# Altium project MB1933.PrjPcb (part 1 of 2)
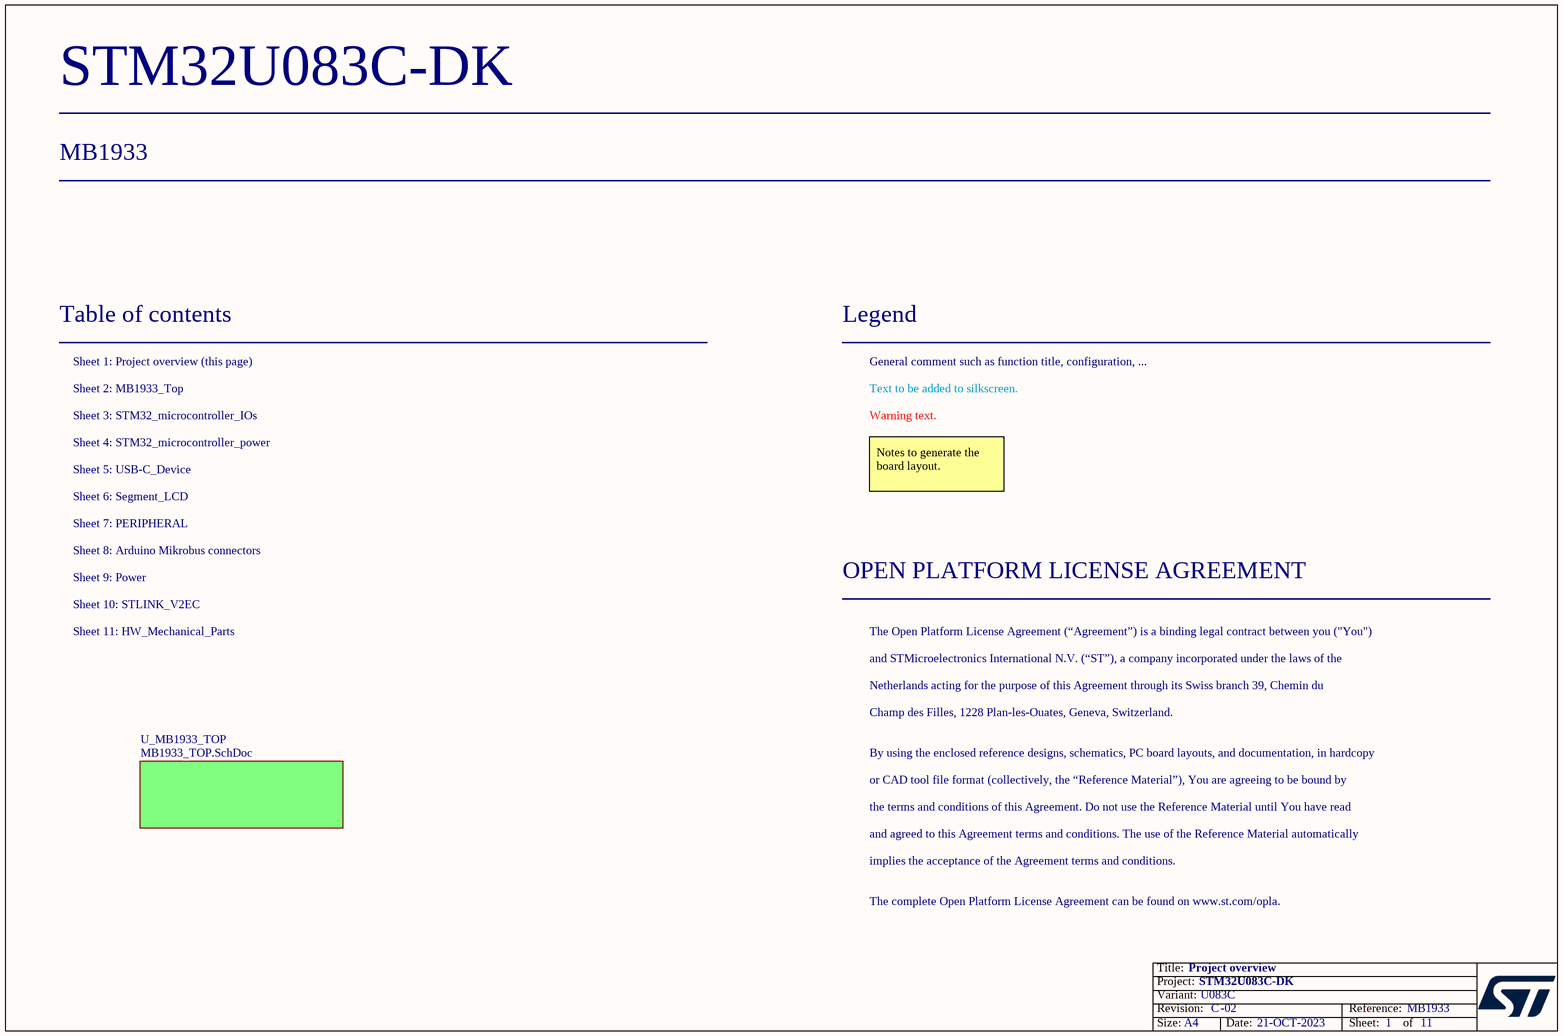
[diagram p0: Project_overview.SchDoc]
VariantName: U083C; Board_Reference: MB1933; Board_PCB_Revision: C; Board_Name: STM32U083C-DK; Board_Document_Date: 21-OCT-2023; Board_Assembly_Revision: 02
11 sheets, 236 parts. Net scope: flat (ports and power ports of the same name join across sheets).
Board file: MB1933.PcbDoc
Sheets:
  Project_overview.SchDoc
    U_MB1933_TOP = MB1933_TOP.SchDoc
      U_STM32_microcontroller_IOs = STM32_microcontroller_IOs.SchDoc
      U_HW_Mechanical_Parts = HW_Mechanical_Parts.SchDoc
      U_Power = Power.SchDoc
      U_Segment_LCD = Segment_LCD.SchDoc
      U_STLINK_V2EC = STLINK_V2EC.SchDoc
      U_USB-C_Device = USB-C_Device.SchDoc
      U_PERIPHERAL = PERIPHERAL.SchDoc
      U_STM32_microcontroller_power = STM32_microcontroller_power.SchDoc
      U_Arduino_Mikrobus_connectors = Arduino_Mikrobus_connectors.SchDoc

## Sheet Project_overview.SchDoc: Project overview
size A4; Date: Not used; ApprovedBy: Not used; CheckedBy: Not used; Author: Not used; CompanyName: STMicroelectronics; DrawnBy: Not used; Engineer: Not used; Organization: Not used; Address1: Not used; Address2: Not used; Address3: Not used; Address4: Not used; DocumentNumber: 1; Revision: Not used; SheetNumber: 1; SheetTotal: 11

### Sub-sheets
U_MB1933_TOP = MB1933_TOP.SchDoc: no entries

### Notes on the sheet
- Table of contents
- Sheet 1: Project overview (this page)
- Legend
- General comment such as function title, configuration, ...
- Sheet 2: MB1933_Top
- Sheet 3: STM32_microcontroller_IOs
- Sheet 4: STM32_microcontroller_power
- Text to be added to silkscreen.
- Warning text.
- Sheet 6: Segment_LCD
- Sheet 5: USB-C_Device
- Notes to generate the board layout.
- Sheet 9: Power
- Sheet 8: Arduino Mikrobus connectors
- Sheet 7: PERIPHERAL
- OPEN PLATFORM LICENSE AGREEMENT
- Sheet 10: STLINK_V2EC
- Sheet 11: HW_Mechanical_Parts
- The Open Platform License Agreement (“Agreement”) is a binding legal contract between you ("You")
- and STMicroelectronics International N.V. (“ST”), a company incorporated under the laws of the
- Netherlands acting for the purpose of this Agreement through its Swiss branch 39, Chemin du
- Champ des Filles, 1228 Plan-les-Ouates, Geneva, Switzerland.
- By using the enclosed reference designs, schematics, PC board layouts, and documentation, in hardcopy
- or CAD tool file format (collectively, the “Reference Material”), You are agreeing to be bound by
- the terms and conditions of this Agreement. Do not use the Reference Material until You have read
- and agreed to this Agreement terms and conditions. The use of the Reference Material automatically
- implies the acceptance of the Agreement terms and conditions.
- The complete Open Platform License Agreement can be found on www.st.com/opla.

## Sheet MB1933_TOP.SchDoc: TOP
size A4; CompanyName: STMicroelectronics; Organization: Microcontrollers Division; SheetNumber: 2; SheetTotal: 11
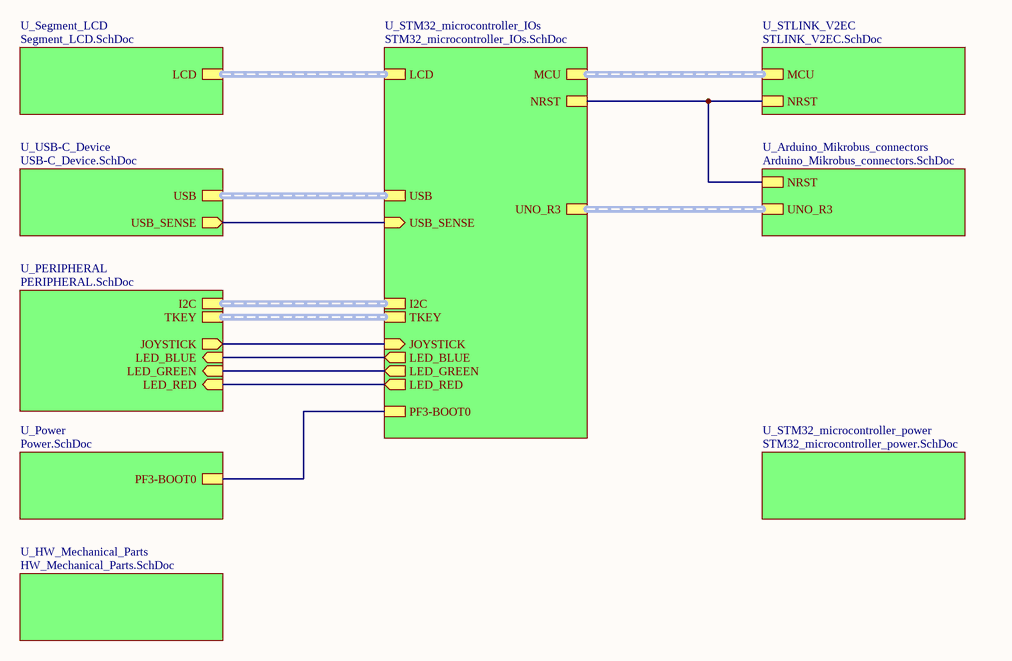
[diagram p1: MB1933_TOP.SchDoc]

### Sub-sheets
U_Arduino_Mikrobus_connectors = Arduino_Mikrobus_connectors.SchDoc: NRST, UNO_R3 (harness UNO_R3)
U_HW_Mechanical_Parts = HW_Mechanical_Parts.SchDoc: no entries
U_PERIPHERAL = PERIPHERAL.SchDoc: LED_BLUE (in), LED_GREEN (in), LED_RED (in), JOYSTICK (out), I2C (harness I2C), TKEY (harness TKEY)
U_Power = Power.SchDoc: PF3-BOOT0
U_Segment_LCD = Segment_LCD.SchDoc: LCD (harness LCD)
U_STLINK_V2EC = STLINK_V2EC.SchDoc: MCU (harness MCU), NRST
U_STM32_microcontroller_IOs = STM32_microcontroller_IOs.SchDoc: NRST, UNO_R3 (harness UNO_R3), JOYSTICK (in), LCD (harness LCD), I2C (harness I2C), TKEY (harness TKEY), LED_GREEN (out), LED_RED (out), LED_BLUE (out), USB (harness USB), PF3-BOOT0, MCU (harness MCU), USB_SENSE (in)
U_STM32_microcontroller_power = STM32_microcontroller_power.SchDoc: no entries
U_USB-C_Device = USB-C_Device.SchDoc: USB (harness USB), USB_SENSE (out)

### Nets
(unnamed): sheet U_STM32_microcontroller_IOs/NRST, sheet U_STLINK_V2EC/NRST, sheet U_Arduino_Mikrobus_connectors/NRST
(unnamed): sheet U_STM32_microcontroller_IOs/JOYSTICK, sheet U_PERIPHERAL/JOYSTICK  [a separate net that carries the same name]
(unnamed): sheet U_STM32_microcontroller_IOs/LED_GREEN, sheet U_PERIPHERAL/LED_GREEN  [a separate net that carries the same name]
(unnamed): sheet U_STM32_microcontroller_IOs/LED_RED, sheet U_PERIPHERAL/LED_RED  [a separate net that carries the same name]
(unnamed): sheet U_STM32_microcontroller_IOs/LED_BLUE, sheet U_PERIPHERAL/LED_BLUE  [a separate net that carries the same name]
(unnamed): sheet U_STM32_microcontroller_IOs/PF3-BOOT0, sheet U_Power/PF3-BOOT0  [a separate net that carries the same name]
(unnamed): sheet U_STM32_microcontroller_IOs/USB_SENSE, sheet U_USB-C_Device/USB_SENSE  [a separate net that carries the same name]

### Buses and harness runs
harness sheet U_Arduino_Mikrobus_connectors/UNO_R3 = sheet U_STM32_microcontroller_IOs/UNO_R3
harness sheet U_PERIPHERAL/I2C = sheet U_STM32_microcontroller_IOs/I2C
harness sheet U_PERIPHERAL/TKEY = sheet U_STM32_microcontroller_IOs/TKEY
harness sheet U_Segment_LCD/LCD = sheet U_STM32_microcontroller_IOs/LCD
harness sheet U_STLINK_V2EC/MCU = sheet U_STM32_microcontroller_IOs/MCU
harness sheet U_STM32_microcontroller_IOs/USB = sheet U_USB-C_Device/USB

## Sheet STM32_microcontroller_IOs.SchDoc: STM32_microcontroller_IOs
size A4; CompanyName: STMicroelectronics; Organization: Microcontrollers Division; SheetNumber: 3; SheetTotal: 11
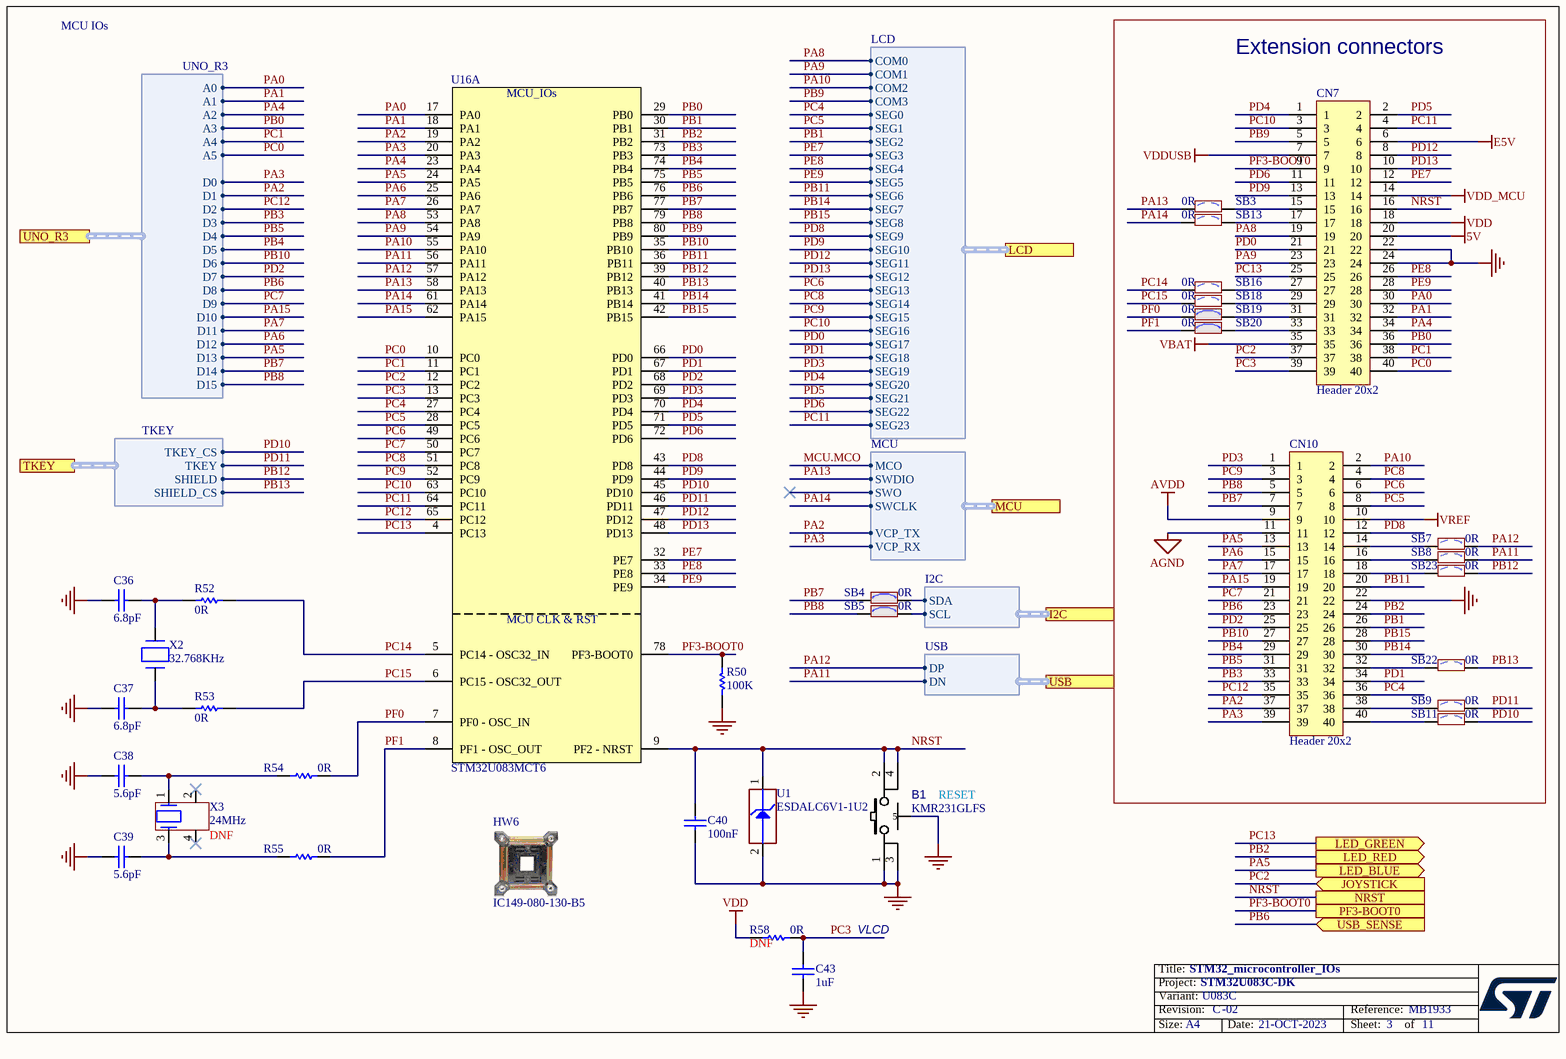
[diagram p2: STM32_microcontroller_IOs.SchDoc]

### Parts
B1  value KMR231GLFS  [SWI_C&K_Y78B23110FP__ITT_KMR231GLFS]  (hidden comment: SW-PUSH-CMS_KMR2_BLACK)
C36  value 6.8pF  [C0402]  (hidden comment: Capacitor)
C37  value 6.8pF  [C0402]  (hidden comment: Capacitor)
C38  value 5.6pF  [C0402]  (hidden comment: Capacitor)
C39  value 5.6pF  [C0402]  (hidden comment: Capacitor)
C40  value 100nF  [C0402]  (hidden comment: Capacitor)
C43  value 1uF  [C0603]  (hidden comment: Capacitor)
CN7  Header 20x2  [CON_SAMTEC_TSW-120-09-G-D]
CN10  Header 20x2  [CON_SAMTEC_TSW-120-09-G-D]
HW6  value IC149-080-130-B5  (hidden comment: SOCKET_LQFP)  (mechanical)
R50  value 100K  [R0402]  (hidden comment: Resistor)
R52  value 0R  [R0402]  (hidden comment: Resistor)
R53  value 0R  [R0402]  (hidden comment: Resistor)
R54  value 0R  [R0402]  (hidden comment: Resistor)
R55  value 0R  [R0402]  (hidden comment: Resistor)
R58  value 0R  [R0402]  (hidden comment: Resistor)
SB3  value 0R  [SOLDER-BRIDGE_R0603-0R]  (hidden comment: SB_OFF)
SB4  value 0R  [SOLDER-BRIDGE_R0603-0R]  (hidden comment: SB_ON)
SB5  value 0R  [SOLDER-BRIDGE_R0603-0R]  (hidden comment: SB_ON)
SB7  value 0R  [SOLDER-BRIDGE_R0603-0R]  (hidden comment: SB_OFF)
SB8  value 0R  [SOLDER-BRIDGE_R0603-0R]  (hidden comment: SB_OFF)
SB9  value 0R  [SOLDER-BRIDGE_R0603-0R]  (hidden comment: SB_OFF)
SB11  value 0R  [SOLDER-BRIDGE_R0603-0R]  (hidden comment: SB_OFF)
SB13  value 0R  [SOLDER-BRIDGE_R0603-0R]  (hidden comment: SB_OFF)
SB16  value 0R  [SOLDER-BRIDGE_R0603-0R]  (hidden comment: SB_OFF)
SB18  value 0R  [SOLDER-BRIDGE_R0603-0R]  (hidden comment: SB_OFF)
SB19  value 0R  [SOLDER-BRIDGE_R0603-0R]  (hidden comment: SB_ON)
SB20  value 0R  [SOLDER-BRIDGE_R0603-0R]  (hidden comment: SB_ON)
SB22  value 0R  [SOLDER-BRIDGE_R0603-0R]  (hidden comment: SB_OFF)
SB23  value 0R  [SOLDER-BRIDGE_R0603-0R]  (hidden comment: SB_OFF)
U1  value ESDALC6V1-1U2  [ESD_ST0201]  (hidden comment: ESD-TRANSIL)
U16  STM32U083MCT6  [ICC_LQFP80_12X12_P050_SOCKET_YAMAICHI_IC149-080-130-B5]  (part A of 2)
X2  value 32.768KHz  [CRY_NX2012SA_2P]  (hidden comment: XTAL_2_PINS)
X3  value 24MHz  [CRY_NX2016SA_4P]  (hidden comment: XTAL_4_PINS)

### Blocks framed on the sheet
Extension connectors: CN7 CN10 SB3 SB7-SB9 SB11 SB13 SB16 SB18-SB20 SB22 SB23

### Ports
I2C (harness I2C), JOYSTICK (in), LCD (harness LCD), LED_BLUE (out), LED_GREEN (out), LED_RED (out), MCU (harness MCU), NRST, PF3-BOOT0, TKEY (harness TKEY), UNO_R3 (harness UNO_R3), USB (harness USB), USB_SENSE (in)

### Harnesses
TKEY: TKEY_CS, TKEY, SHIELD, SHIELD_CS
LCD: COM0, COM1, COM2, COM3, SEG0, SEG1, SEG2, SEG3, SEG4, SEG5, SEG6, SEG7, SEG8, SEG9, SEG10, SEG11, SEG12, SEG13, SEG14, SEG15, SEG16, SEG17, SEG18, SEG19, SEG20, SEG21, SEG22, SEG23
I2C: SDA, SCL
USB: DP, DN
UNO_R3: A0, A1, A2, A3, A4, A5, D0, D1, D2, D3, D4, D5, D6, D7, D8, D9, D10, D11, D12, D13, D14, D15
MCU: MCO, SWDIO, SWO, VCP_TX, SWCLK, VCP_RX

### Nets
5V: CN7.20
AGND: CN10.11
AVDD: CN10.9
E5V: CN7.6
GND: B1.1 B1.3 B1.5 C36.1 C37.1 C38.1 C39.1 C40.1 C43.1 CN7.22 CN7.24 CN10.22 R50.2 U1.2(GND)
VBAT: CN7.35
VDD: CN7.18 R58.1
VDD_MCU: CN7.14
VDDUSB: CN7.7
VREF: CN10.10
I2C_SCL: SB5.2 ; port I2C.SCL
I2C_SDA: SB4.2 ; port I2C.SDA
NRST: B1.2 B1.4 C40.2 CN7.16 U1.1(IO1) U16.9(PF2_-_NRST) ; port NRST
PA0: CN7.30 U16.17(PA0) ; port UNO_R3.A0  [project net ARD_A0]
PA1: CN7.32 U16.18(PA1) ; port UNO_R3.A1  [project net ARD_A1]
PA2: CN10.37 U16.19(PA2) ; port UNO_R3.D1, port MCU.VCP_TX  [project net ARD_D1]
PA3: CN10.39 U16.20(PA3) ; port UNO_R3.D0, port MCU.VCP_RX  [project net ARD_D0]
PA4: CN7.34 U16.23(PA4) ; port UNO_R3.A2  [project net ARD_A2]
PA5: CN10.13 U16.24(PA5) ; port LED_BLUE, port UNO_R3.D13  [project net ARD_D13]
PA6: CN10.15 U16.25(PA6) ; port UNO_R3.D12  [project net ARD_D12]
PA7: CN10.17 U16.26(PA7) ; port UNO_R3.D11  [project net ARD_D11]
PA8: CN7.19 U16.53(PA8) ; port LCD.COM0  [project net COM0]
PA9: CN7.23 U16.54(PA9) ; port LCD.COM1  [project net COM1]
PA10: CN10.2 U16.55(PA10) ; port LCD.COM2  [project net COM2]
PA11: SB8.2 U16.56(PA11) ; port USB.DN
PA12: SB7.2 U16.57(PA12) ; port USB.DP
PA13: SB3.1 U16.58(PA13) ; port MCU.SWDIO  [project net MCU.SWDIO]
PA14: SB13.1 U16.61(PA14) ; port MCU.SWCLK  [project net MCU.SWCLK]
PA15: CN10.19 U16.62(PA15) ; port UNO_R3.D10  [project net ARD_D10]
PB0: CN7.36 U16.29(PB0) ; port UNO_R3.A3  [project net ARD_A3]
PB1: CN10.26 U16.30(PB1) ; port LCD.SEG2
PB2: CN10.24 U16.31(PB2) ; port LED_RED
PB3: CN10.33 U16.73(PB3) ; port UNO_R3.D3  [project net ARD_D3]
PB4: CN10.29 U16.74(PB4) ; port UNO_R3.D5  [project net ARD_D5]
PB5: CN10.31 U16.75(PB5) ; port UNO_R3.D4  [project net ARD_D4]
PB6: CN10.23 U16.76(PB6) ; port USB_SENSE, port UNO_R3.D8  [project net ARD_D8]
PB7: CN10.7 SB4.1 U16.77(PB7) ; port UNO_R3.D14  [project net ARD_D14]
PB8: CN10.5 SB5.1 U16.79(PB8) ; port UNO_R3.D15  [project net ARD_D15]
PB9: CN7.5 U16.80(PB9) ; port LCD.COM3  [project net COM3]
PB10: CN10.27 U16.35(PB10) ; port UNO_R3.D6  [project net ARD_D6]
PB11: CN10.20 U16.36(PB11) ; port LCD.SEG6
PB12: SB23.2 U16.39(PB12) ; port TKEY.SHIELD
PB13: SB22.2 U16.40(PB13) ; port TKEY.SHIELD_CS
PB14: CN10.30 U16.41(PB14) ; port LCD.SEG7
PB15: CN10.28 U16.42(PB15) ; port LCD.SEG8
PC0: CN7.40 U16.10(PC0) ; port UNO_R3.A5  [project net ARD_A5]
PC1: CN7.38 U16.11(PC1) ; port UNO_R3.A4  [project net ARD_A4]
PC2: CN7.37 U16.12(PC2) ; port JOYSTICK
PC3: C43.2 CN7.39 R58.2 U16.13(PC3)
PC4: CN10.36 U16.27(PC4) ; port LCD.SEG0
PC5: CN10.8 U16.28(PC5) ; port LCD.SEG1
PC6: CN10.6 U16.49(PC6) ; port LCD.SEG13
PC7: CN10.21 U16.50(PC7) ; port UNO_R3.D9  [project net ARD_D9]
PC8: CN10.4 U16.51(PC8) ; port LCD.SEG14
PC9: CN10.3 U16.52(PC9) ; port LCD.SEG15
PC10: CN7.3 U16.63(PC10) ; port LCD.SEG16
PC11: CN7.4 U16.64(PC11) ; port LCD.SEG23
PC12: CN10.35 U16.65(PC12) ; port UNO_R3.D2  [project net ARD_D2]
PC13: CN7.25 U16.4(PC13) ; port LED_GREEN
PC14: R52.2 SB16.1 U16.5(PC14_-_OSC32_IN)
PC15: R53.2 SB18.1 U16.6(PC15_-_OSC32_OUT)
PD0: CN7.21 U16.66(PD0) ; port LCD.SEG17
PD1: CN10.34 U16.67(PD1) ; port LCD.SEG18
PD2: CN10.25 U16.68(PD2) ; port UNO_R3.D7  [project net ARD_D7]
PD3: CN10.1 U16.69(PD3) ; port LCD.SEG19
PD4: CN7.1 U16.70(PD4) ; port LCD.SEG20
PD5: CN7.2 U16.71(PD5) ; port LCD.SEG21
PD6: CN7.11 U16.72(PD6) ; port LCD.SEG22
PD8: CN10.12 U16.43(PD8) ; port LCD.SEG9
PD9: CN7.13 U16.44(PD9) ; port LCD.SEG10
PD10: SB11.2 U16.45(PD10) ; port TKEY.TKEY_CS
PD11: SB9.2 U16.46(PD11) ; port TKEY.TKEY
PD12: CN7.8 U16.47(PD12) ; port LCD.SEG11
PD13: CN7.10 U16.48(PD13) ; port LCD.SEG12
PE7: CN7.12 U16.32(PE7) ; port LCD.SEG3
PE8: CN7.26 U16.33(PE8) ; port LCD.SEG4
PE9: CN7.28 U16.34(PE9) ; port LCD.SEG5
PF0: R54.2 SB19.1 U16.7(PF0_-_OSC_IN)
PF1: R55.2 SB20.1 U16.8(PF1_-_OSC_OUT)
PF3-BOOT0: CN7.9 R50.1 U16.78(PF3-BOOT0) ; port PF3-BOOT0
NetC36_2: C36.2 R52.1 X2.2(X2)
NetC37_2: C37.2 R53.1 X2.1(X1)
NetC38_2: C38.2 R54.1 X3.1
NetC39_2: C39.2 R55.1 X3.3
NetCN7_15: CN7.15 SB3.2
NetCN7_17: CN7.17 SB13.2
NetCN7_27: CN7.27 SB16.2
NetCN7_29: CN7.29 SB18.2
NetCN7_31: CN7.31 SB19.2
NetCN7_33: CN7.33 SB20.2
NetCN10_14: CN10.14 SB7.1
NetCN10_16: CN10.16 SB8.1
NetCN10_18: CN10.18 SB23.1
NetCN10_32: CN10.32 SB22.1
NetCN10_38: CN10.38 SB9.1
NetCN10_40: CN10.40 SB11.1

Not connected (* = marked no-connect by the designer): X3 2* 4*

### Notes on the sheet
- MCU IOs
- (near X3) DNF
- (near B1) RESET
- (near R58) DNF
- VLCD

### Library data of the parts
B1 = MCD-01485: Switch tactile, SPST-NO, 32V, 50mA, 2.8x4.6mm; Part_Type: Misc; Part_Preference: Recommended; Manufacturer: C&K; Component_Country_Of_Origin: France; ShowFields: YES; ID: 3585; Order_Code_RS: 505-9192
C36 C37 = MCD-00674: Capacitor, MLCC, 6.8pF, 50V, NPO, +/-0.25pF, 0402, T=0.5mm; Manufacturer_Part_Number: CC0402CRNPO9BN6R8; Manufacturer: YAGEO; Part_Preference: Recommended; Component_Country_Of_Origin: China; ShowFields: YES; ID: 3068
C38 C39 = MCD-01374: Capacitor, MLCC, 5.6pF, 50V, NPO, +/-0.1pF, 0402, T=0.5mm; Manufacturer_Part_Number: CC0402BRNPO9BN5R6; Manufacturer: YAGEO; Part_Preference: Recommended; Component_Country_Of_Origin: China; ShowFields: YES; ID: 3474
C40 = MCD-00006: Capacitor, MLCC, 100nF, 16V, X7R, +/-10%, 0402, T=0.5mm; Part_Preference: Recommended; Manufacturer: YAGEO; Manufacturer_Part_Number: CC0402KRX7R7BB104; Partial_Alternate_Internal_Part_Number: MCD-03299; Order_Code_RS: 9402047; Component_Country_Of_Origin: China; ShowFields: YES; ID: 2474
C43 = MCD-00010: Capacitor, MLCC, 1uF, 16V, X5R, +/-10%, 0603, T=0.8mm; Manufacturer_Part_Number: CC0603KRX5R7BB105; Manufacturer: YAGEO; Part_Preference: Recommended; Order_Code_RS: 2370680; Component_Country_Of_Origin: China; ShowFields: YES; ID: 2470
CN7 CN10 = MCD-03295: Header, 20x2, 2.54mm, VR, TH, T=5.84mm/10.16mm; Part_Type: Connector; Part_Preference: Recommended; Manufacturer: SAMTEC; Manufacturer_Part_Number: TSW-120-09-G-D; ShowFields: YES; ID: 5411; Component_Country_Of_Origin: USA°
HW6 = MCD-03172: Socket_IC, LQFP80, IC149 series, pitch 0.5mm, T=11mm; Part_Preference: Recommended; Manufacturer: YAMAICHI; ShowFields: YES; ID: 5288
R50 = MCD-00059: Resistor, 100K, 0402, +/-1%, 1/16W; Manufacturer_Part_Number: RC0402FR-07100KL; Manufacturer: YAGEO; Part_Preference: Recommended; Partial_Alternate_Internal_Part_Number: MCD-03301; Order_Code_RS: 2421891; Component_Country_Of_Origin: China; ShowFields: YES; ID: 2533
R52-R55 R58 = MCD-00052: Resistor, 0R, 0402, +/-5%, 1/16W; Manufacturer_Part_Number: RC0402JR-070RL; Manufacturer: YAGEO; Part_Preference: Recommended; Order_Code_RS: 9232516RL; Component_Country_Of_Origin: China; ShowFields: YES; ID: 2540
SB3 SB9 SB11 SB13 SB16 SB18 SB22 SB23 = MCD-00072: Resistor, 0R, SB0603, 5%, 0.1W; Manufacturer_Part_Number: RC0603JR-070RL; Manufacturer: YAGEO; Part_Preference: Recommended; Manufacturer_HQ_COO: Unknown; Component_Country_Of_Origin: China; ShowFields: YES; ID: 2520; Order_Code_RS: 199-5647
SB4 SB5 SB19 SB20 = MCD-00071: Resistor, 0R, SB0603, 5%, 0.1W; Manufacturer_Part_Number: RC0603JR-070RL; Manufacturer: YAGEO; Part_Preference: Recommended; Manufacturer_HQ_COO: Unknown; ShowFields: YES; ID: 2521; Order_Code_RS: 199-5647; Component_Country_Of_Origin: China
SB7 SB8 = MCD-00072: Resistor, 0R, SB0603, 5%, 0.1W; Manufacturer_Part_Number: RC0603JR-070RL; Manufacturer: YAGEO; Part_Preference: Recommended; Manufacturer_HQ_COO: Unknown; ShowFields: YES; ID: 2520; Component_Country_Of_Origin: China; Order_Code_RS: 199-5647
U1 = MCD-00170: Diode, ESD TVS, 3V, 100nA, 8V, ST0201; Manufacturer: STMICROELECTRONICS; BMS_Part_Number: 9151132; Part_Preference: Recommended; Manufacturer_HQ_COO: EU; Component_Country_Of_Origin: China; ShowFields: YES; ID: 2696; Order_Code_RS: 795-8404
U16 = MCD-03131: Arm® Cortex®-M0+ 32-bit MCU,  256K Flash memory, with LQFP80 socket footprint (IC149-080-130-B5); Part_Type: IC; Part_Preference: Recommended; Manufacturer: STMICROELECTRONICS; Component_Country_Of_Origin: Unknown; ShowFields: YES; ID: 5247
X2 = MCD-01479: Crystal, 32.768kHz, 6pF, +/-20ppm, 80K, 2.05x1.2mm; Part_Type: Crystal_Osc; Manufacturer_Part_Number: NX2012SA-32.768KHZ-EXS00A-MU00527; Manufacturer: NDK; BMS_Part_Number: 9157049; Part_Preference: Recommended; Component_Country_Of_Origin: Unknown; ShowFields: YES; ID: 3579
X3 = MCD-01036: Crystal, 24MHz, 6pF, +/-20ppm, 80R, 2x1.6mm; Part_Type: Crystal_Osc; Manufacturer_Part_Number: NX2016SA-24MHZ-EXS00A-CS10820; Manufacturer: NDK; BMS_Part_Number: 9157045; Part_Preference: Recommended; Component_Country_Of_Origin: Unknown; ShowFields: YES; ID: 2989

## Sheet HW_Mechanical_Parts.SchDoc: HW Mechanical parts
size A4; SheetNumber: 11; SheetTotal: 11
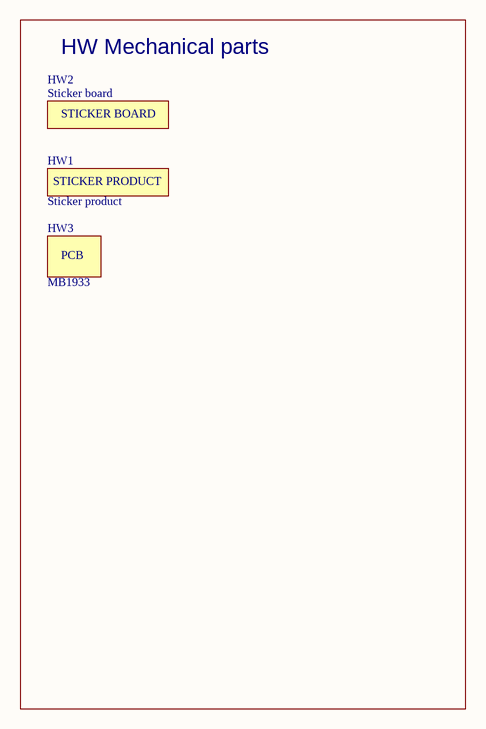
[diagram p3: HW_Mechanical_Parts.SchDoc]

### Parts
HW1  value Sticker product  [STICKER_PRODUCT_25X9]  (hidden comment: STICKER_PRODUCT)  (no BOM)
HW2  value Sticker board  [STICKER_BOARD_25X9]  (hidden comment: STICKER_BOARD)  (no BOM)
HW3  value MB1933  (hidden comment: PCB)  (no BOM)

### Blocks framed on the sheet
HW Mechanical parts: HW1-HW3

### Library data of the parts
HW1 = MCD-00547: Sticker product 25x9 mm; Part_Type: Misc; Part_Preference: Recommended; ShowFields: YES; ID: 3197
HW2 = MCD-00235: Sticker Board 25x9 mm; Part_Type: Misc; Part_Preference: Recommended; ShowFields: YES; ID: 2632
HW3 = MCD-03168: MB1933 PCB; Part_Preference: Recommended; ShowFields: YES; ID: 5284

## Sheet Power.SchDoc: Power
size A4; CompanyName: STMicroelectronics; Organization: Microcontrollers Division; SheetNumber: 9; SheetTotal: 11
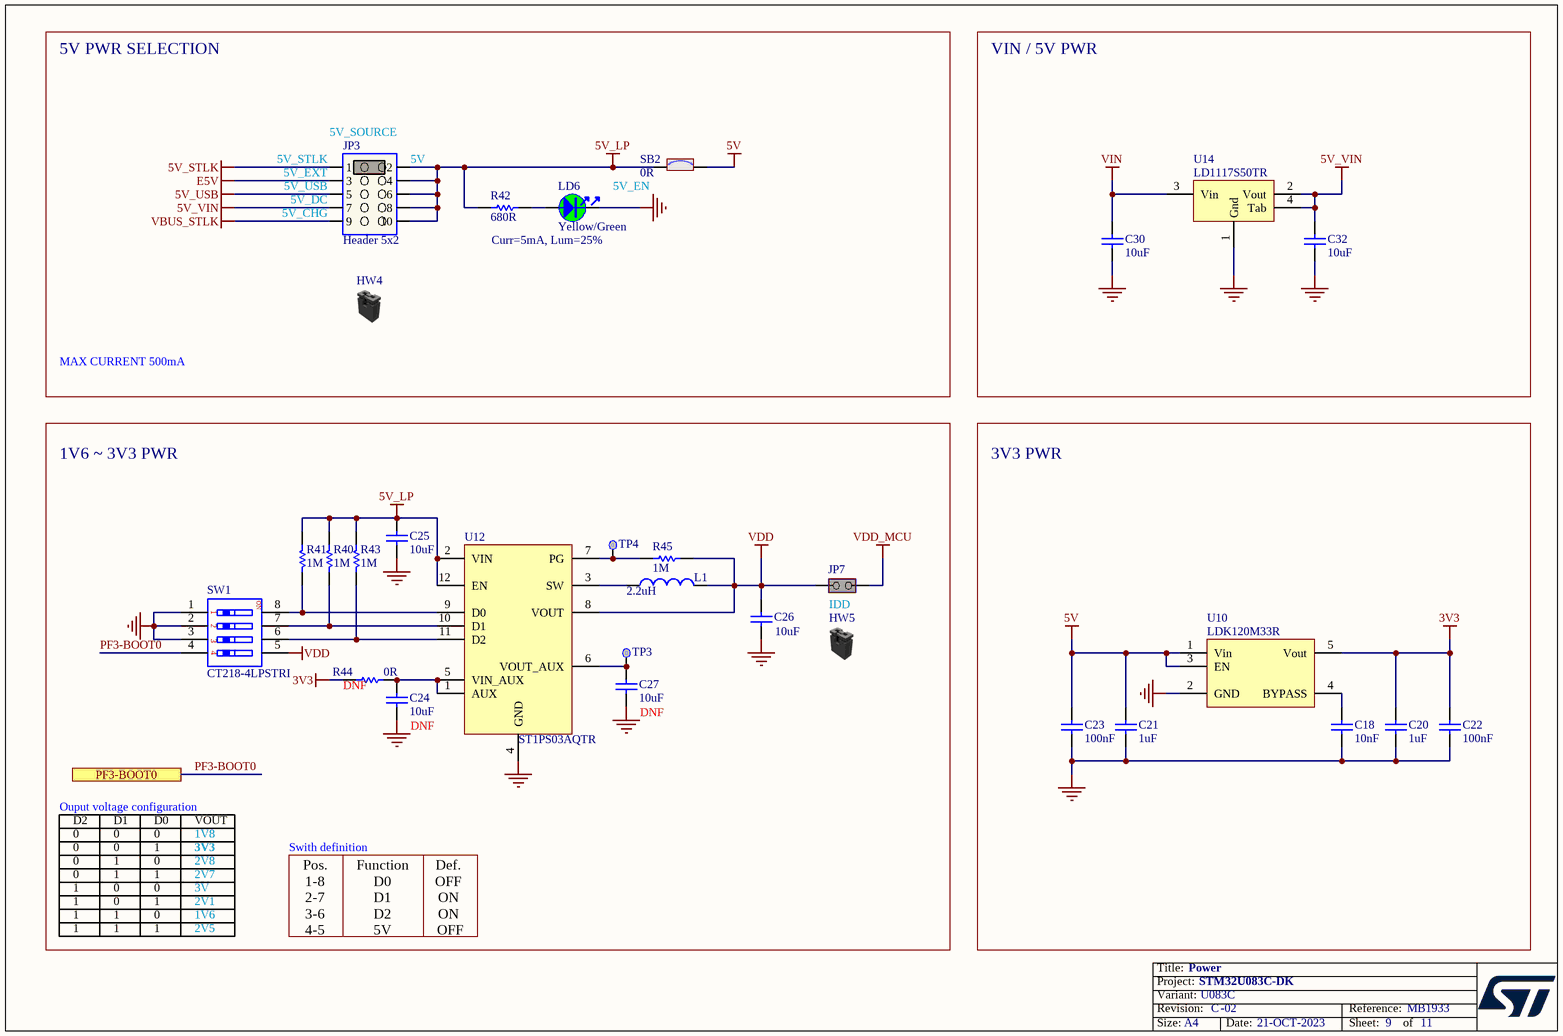
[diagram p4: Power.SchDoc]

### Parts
C18  value 10nF  [C0402]  (hidden comment: Capacitor)
C20  value 1uF  [C0603]  (hidden comment: Capacitor)
C21  value 1uF  [C0603]  (hidden comment: Capacitor)
C22  value 100nF  [C0402]  (hidden comment: Capacitor)
C23  value 100nF  [C0402]  (hidden comment: Capacitor)
C24  value 10uF  [C0603]  (hidden comment: Capacitor)
C25  value 10uF  [C0603]  (hidden comment: Capacitor)
C26  value 10uF  [C0603]  (hidden comment: Capacitor)
C27  value 10uF  [C0603]  (hidden comment: Capacitor)
C30  value 10uF  [C0805]  (hidden comment: Capacitor)
C32  value 10uF  [C0805]  (hidden comment: Capacitor)
HW4  Shunt Black 2.54mm  (value not drawn)  (mechanical)
HW5  Shunt Black 2.54mm  (value not drawn)  (mechanical)
JP3  value Header 5x2  [CON_SAMTEC_TSW-105-07-X-D]  (hidden comment: Jumper_Header 5x2 Fitted 1-2)
JP7  Jumper_Header 2x1 Fitted  [CON_SAMTEC_TSW-102-07-G-S]  (value not drawn)
L1  value 2.2uH  [IND_TDK_VLS252010HBX-1]  (hidden comment: Inductor)
LD6  value Yellow/Green  [LED_0402_EVERLIGHT_16-213SYGC/S530-E3-TR8 _YELLOW-GREEN_1A2K_H0P45]  (hidden comment: LED_green)
R40  value 1M  [R0402]  (hidden comment: Resistor)
R41  value 1M  [R0402]  (hidden comment: Resistor)
R42  value 680R  [R0402]  (hidden comment: Resistor)
R43  value 1M  [R0402]  (hidden comment: Resistor)
R44  value 0R  [R0402]  (hidden comment: Resistor)
R45  value 1M  [R0402]  (hidden comment: Resistor)
SB2  value 0R  [SOLDER-BRIDGE_R0603-0R]  (hidden comment: SB_ON)
SW1  value CT218-4LPSTRI  [SWI_CTS_CTS218-4LP]  (hidden comment: SWITCH_4WAY)
TP3  Test Point  [TP_SMD_1MM]  (value not drawn)  (no BOM)
TP4  Test Point  [TP_SMD_1MM]  (value not drawn)  (no BOM)
U10  LDK120M33R  [REG_SOT23-5L]
U12  value ST1PS03AQTR  [ICC_TQFN12_2X1P7_P040]  (hidden comment: ST1PS03)
U14  LD1117S50TR  [REG_SOT223-TAB]

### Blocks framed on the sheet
5V PWR SELECTION: HW4 JP3 LD6 R42 SB2
VIN / 5V PWR: C30 C32 U14
1V6 ~ 3V3 PWR: C24-C27 HW5 JP7 L1 R40 R41 R43-R45 SW1 TP3 TP4 U12
3V3 PWR: C18 C20-C23 U10

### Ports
PF3-BOOT0

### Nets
3V3: C20.2 C22.2 R44.1 U10.5(Vout)
5V: C21.2 C23.2 SB2.2 U10.1(Vin) U10.3(EN)
5V_LP: C25.2 JP3.2 JP3.4 JP3.6 JP3.8 JP3.10 R40.1 R41.1 R42.1 R43.1 SB2.1 U12.2(VIN) U12.12(EN)
5V_STLK: JP3.1
5V_USB: JP3.5
5V_VIN: C32.2 JP3.7 U14.2(Vout) U14.4(Tab)
E5V: JP3.3
GND: C18.1 C20.1 C21.1 C22.1 C23.1 C24.1 C25.1 C26.1 C27.1 C30.1 C32.1 LD6.2 SW1.1 SW1.2 SW1.3 U10.2(GND) U12.4(GND) U14.1(Gnd)
VBUS_STLK: JP3.9
VDD: C26.2 JP7.2(NO) L1.2 R45.1 SW1.5 U12.8(VOUT)
VDD_MCU: JP7.1(COMMON)
VIN: C30.2 U14.3(Vin)
PF3-BOOT0: SW1.4 ; port PF3-BOOT0
NetC18_2: C18.2 U10.4(BYPASS)
NetC24_2: C24.2 R44.2 U12.1(AUX) U12.5(VIN_AUX)
NetC27_2: C27.2 TP3.1 U12.6(VOUT_AUX)
NetL1_1: L1.1 U12.3(SW)
NetLD6_1: LD6.1 R42.2
NetR40_2: R40.2 SW1.7 U12.10(D1)
NetR41_2: R41.2 SW1.8 U12.9(D0)
NetR43_2: R43.2 SW1.6 U12.11(D2)
NetR45_2: R45.2 TP4.1 U12.7(PG)

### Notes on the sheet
- (near JP3) 5V_STLK
- (near JP3) 5V_EXT
- (near JP3) 5V_SOURCE
- (near JP3) 5V
- (near JP3) 5V_USB
- (near JP3) 5V_CHG
- (near JP3) 5V_DC
- Curr=5mA, Lum=25%
- 5V_EN
- MAX CURRENT 500mA
- IDD
- (near R44) DNF
- (near C27) DNF
- (near C24) DNF
- Ouput voltage configuration
- D2
- 0
- D1
- D0
- 1
- VOUT
- 1V8
- 3V3
- Swith definition
- 2V8
- 2V7
- 3V
- 2V1
- 1V6
- 2V5
- Pos.
  1-8
  2-7
  3-6
  4-5
- Function
  D0
  D1
  D2
  5V
- Def.
  OFF
  ON
  ON
  OFF

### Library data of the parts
C18 = MCD-02198: Capacitor, MLCC, 10nF, 50V, X7R, +/-10%, 0402, T=0.5mm; Manufacturer_Part_Number: CC0402KRX7R9BB103; Manufacturer: YAGEO; Part_Preference: Recommended; Order_Code_RS: 6169644; Component_Country_Of_Origin: China; ShowFields: YES; ID: 4298
C20 C21 = MCD-00010: as C43 on sheet STM32_microcontroller_IOs
C22 C23 = MCD-00006: Capacitor, MLCC, 100nF, 16V, X7R, +/-10%, 0402, T=0.5mm; Manufacturer_Part_Number: CC0402KRX7R7BB104; Manufacturer: YAGEO; Part_Preference: Recommended; Partial_Alternate_Internal_Part_Number: MCD-03299; Order_Code_RS: 9402047; Component_Country_Of_Origin: China; ShowFields: YES; ID: 2474
C24-C27 = MCD-00099: Capacitor, MLCC, 10uF, 10V, X5R, +/-10%, 0603, T=0.8mm; Manufacturer_Part_Number: GRM188R61A106KE69D; Manufacturer: MURATA; Part_Preference: Recommended; Partial_Alternate_Internal_Part_Number: MCD-03152; Order_Code_RS: 2494233; Component_Country_Of_Origin: Japan°°; ShowFields: YES; ID: 2770
C30 C32 = MCD-00014: Capacitor, MLCC, 10uF, 25V, X5R, +/-10%, 0805, T=0.85mm; Manufacturer_Part_Number: CC0805KRX5R8BB106; Manufacturer: YAGEO; Part_Preference: Recommended; Full_Alternate_Internal_Part_Number: MCD-02385; Partial_Alternate_Internal_Part_Number: MCD-03053; Component_Country_Of_Origin: China; ShowFields: YES; ID: 2468
HW4 = MCD-00043: Shunt, 2.54mm, Black, 4.3A, 6.1mm, 5mR; Part_Type: Misc; Manufacturer_Part_Number: SNT-100-BK-G; Manufacturer: SAMTEC; Part_Preference: Recommended; Full_Alternate_Internal_Part_Number: MCD-02388; Manufacturer_HQ_COO: Unknown; Partial_Alternate_Internal_Part_Number: MCD-01849; Value: SNT-100-BK-G; Component_Country_Of_Origin: China, Costa Rica, Malaysia, USA, Vietnam; ShowFields: YES; ID: 2551; Order_Code_RS: 158-7784; Alternate_EMS: A
HW5 = MCD-00043: Shunt, 2.54mm, Black, 4.3A, 6.1mm, 5mR; Manufacturer_Part_Number: SNT-100-BK-G; Manufacturer: SAMTEC; Part_Type: Misc; Part_Preference: Recommended; Full_Alternate_Internal_Part_Number: MCD-02388; Manufacturer_HQ_COO: Unknown; Partial_Alternate_Internal_Part_Number: MCD-01849; Value: SNT-100-BK-G; Component_Country_Of_Origin: China, Costa Rica, Malaysia, USA, Vietnam; ShowFields: YES; ID: 2551; Order_Code_RS: 158-7784; Alternate_EMS: A
JP3 = MCD-01203: Header, 5x2, 2.54mm, VR, TH, T=5.84mm/2.54mm; Part_Type: Connector; Manufacturer_Part_Number: TSW-105-07-G-D; Manufacturer: SAMTEC; BMS_Part_Number: 9083523; Part_Preference: Recommended; Full_Alternate_Internal_Part_Number: MCD-02391; Partial_Alternate_Internal_Part_Number: MCD-03596, MCD-03727; Order_Code_RS: 161-2267; Component_Country_Of_Origin: China, Costa Rica, Malaysia, United States, Vietnam; ShowFields: YES; ID: 3293; Alternate_EMS: A
JP7 = MCD-00683: Header, 2x1, 2.54mm, VR, TH, T=5.84mm/2.54mm; Part_Type: Connector; Manufacturer_Part_Number: TSW-102-07-G-S; Manufacturer: SAMTEC; Part_Preference: Recommended; Full_Alternate_Internal_Part_Number: MCD-02389; Partial_Alternate_Internal_Part_Number: MCD-02957, MCD-03720; Order_Code_RS: 155-5312; Component_Country_Of_Origin: China, Costa Rica, Malaysia, United States, Vietnam; ShowFields: YES; ID: 3057
L1 = MCD-00240: Inductor, 2.2uH, +/-20%, 2.6A, 100mR, 2.5x2mm, T=1mm; Manufacturer_Part_Number: VLS252010HBX-2R2M-1; Manufacturer: TDK; Part_Preference: Recommended; Order_Code_RS: 181-5270; Component_Country_Of_Origin: Unknown; ShowFields: YES; ID: 2627
LD6 = MCD-02330: LED Bicolor, Yellow/Green, 2V, 25mA, 0402; Part_Type: Display; Manufacturer_Part_Number: 16-213SYGC/S530-E3/TR8; Manufacturer: EVERLIGHT; Part_Preference: Recommended; Component_Country_Of_Origin: China; ShowFields: YES; ID: 4436
R40 R41 R43 = MCD-00182: Resistor, 1M, 0402, +/-1%, 1/16W; Manufacturer_Part_Number: RC0402FR-071ML; Manufacturer: YAGEO; Part_Preference: Recommended; BMS_Part_Number: 9131778; Order_Code_RS: 618-6194; Component_Country_Of_Origin: China; ShowFields: YES; ID: 2686
R42 = MCD-00507: Resistor, 680R, 0402, +/-1%, 1/16W; Manufacturer_Part_Number: RC0402FR-07680RL; Manufacturer: YAGEO; Part_Preference: Recommended; Component_Country_Of_Origin: China; ShowFields: YES; ID: 3238
R44 = MCD-00052: Resistor, 0R, 0402, +/-5%, 1/16W; Part_Preference: Recommended; Manufacturer: YAGEO; Manufacturer_Part_Number: RC0402JR-070RL; Order_Code_RS: 9232516RL; Component_Country_Of_Origin: China; ShowFields: YES; ID: 2540
R45 = MCD-00182: Resistor, 1M, 0402, +/-1%, 1/16W; Manufacturer_Part_Number: RC0402FR-071ML; Manufacturer: YAGEO; BMS_Part_Number: 9131778; Part_Preference: Recommended; Order_Code_RS: 618-6194; Component_Country_Of_Origin: China; ShowFields: YES; ID: 2686
SB2 = MCD-00071: as SB4 on sheet STM32_microcontroller_IOs
SW1 = MCD-00167: SMT half pitch DIP switch, SPST, 50V, 100mA, 6.6x6.25mm; Part_Type: Misc; Part_Preference: Recommended; Manufacturer: CTS; Manufacturer_Part_Number: 218-4LPSTR; Component_Country_Of_Origin: Taiwan; ShowFields: YES; ID: 2701
TP3 TP4 = MCD-00074: Test Point 1mm; Part_Type: Misc; Part_Preference: Recommended; ShowFields: YES; ID: 2518; Component_Country_Of_Origin: Unknown
U10 = MCD-00663: LDO, 200mA, Low quiescent current very low noise LDO; Part_Type: IC; Manufacturer: STMICROELECTRONICS; BMS_Part_Number: 9176330; Part_Preference: Recommended; Manufacturer_HQ_COO: EU; Partial_Alternate_Internal_Part_Number: MCD-03279; Order_Code_RS: 188-9202; Component_Country_Of_Origin: China; ShowFields: YES; ID: 3082
U12 = MCD-03133: 400mA Nano-Quiescent Step down converter with Aux switch; Part_Type: IC; Part_Preference: Recommended; Manufacturer: STMICROELECTRONICS; Component_Country_Of_Origin: China; ShowFields: YES; ID: 5249
U14 = MCD-00088: IC REG LDO 5V 0.8A SOT223; Manufacturer: STMICROELECTRONICS; BMS_Part_Number: 9176133; Part_Preference: Recommended; Manufacturer_HQ_COO: EU; Component_Country_Of_Origin: China; ShowFields: YES; ID: 2503

## Sheet Segment_LCD.SchDoc: Segment_LCD
size A4; Author: A.B; CompanyName: STMicroelectronics; Organization: Microcontrollers Division; Address1: 12, Rue Jules HOROWITZ; Address2: 38019 Grenoble; Address3: FRANCE; SheetNumber: 6; SheetTotal: 11
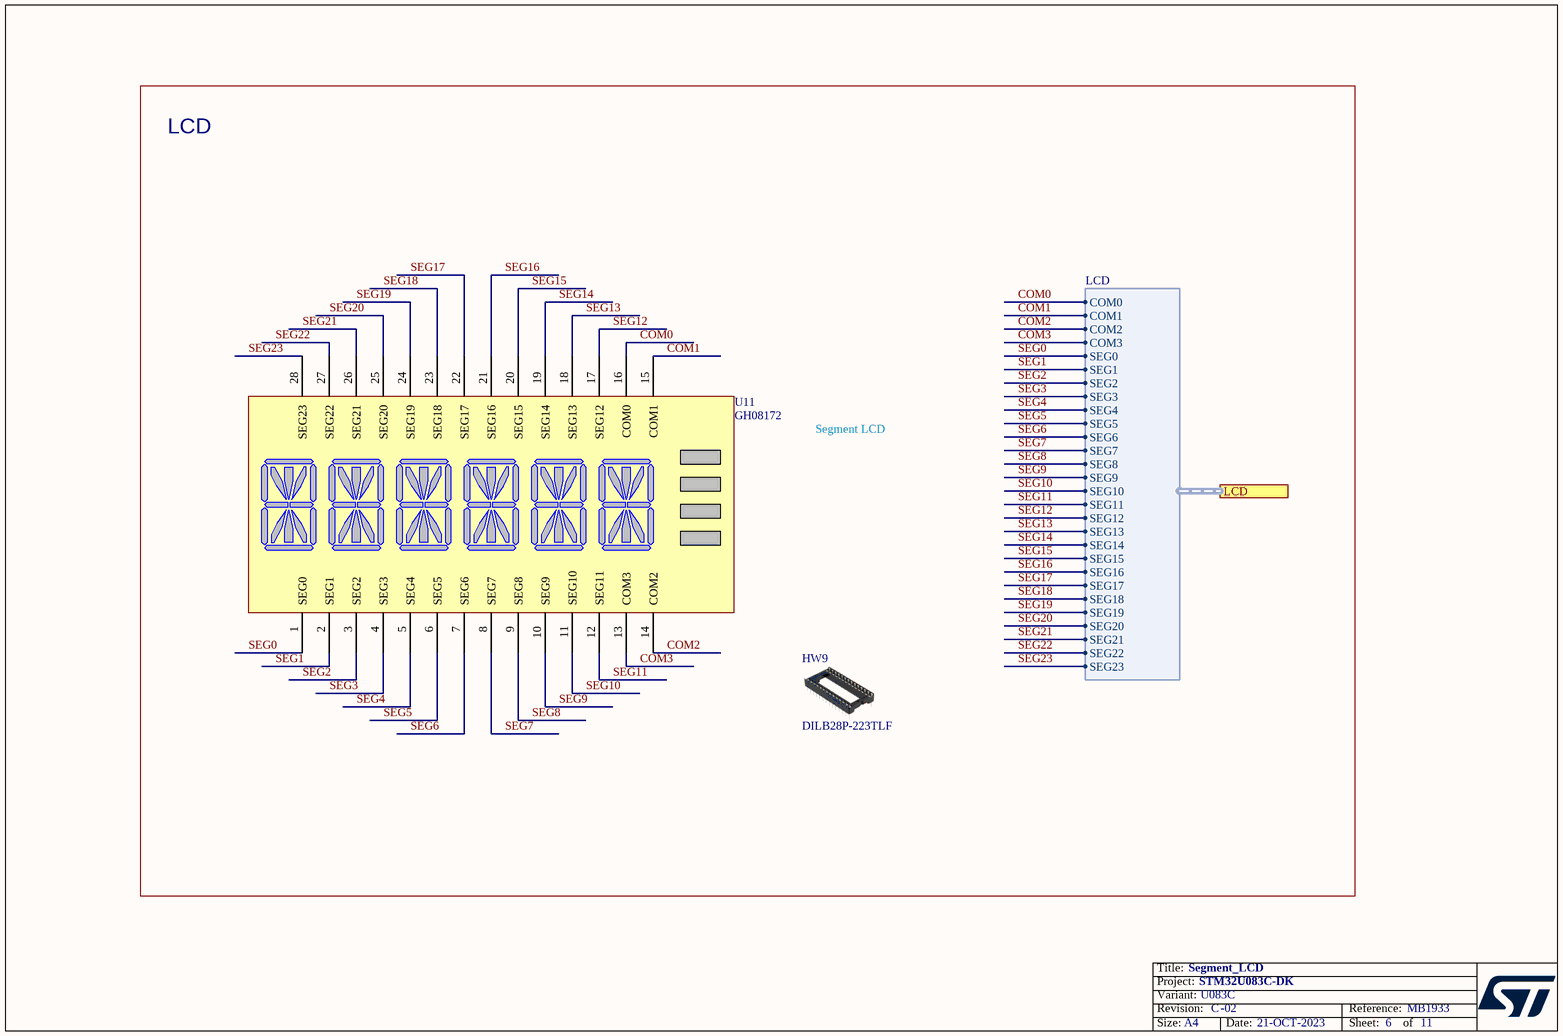
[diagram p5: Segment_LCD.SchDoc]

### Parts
HW9  value DILB28P-223TLF  (hidden comment: DIP28)  (mechanical)
U11  GH08172  [LCD_DISPLAY_GH08172_DIP28]

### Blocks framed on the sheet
LCD: HW9 U11

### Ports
LCD (harness LCD)

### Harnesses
LCD: COM0, COM1, COM2, COM3, SEG0, SEG1, SEG2, SEG3, SEG4, SEG5, SEG6, SEG7, SEG8, SEG9, SEG10, SEG11, SEG12, SEG13, SEG14, SEG15, SEG16, SEG17, SEG18, SEG19, SEG20, SEG21, SEG22, SEG23

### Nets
COM0: U11.16(COM0) ; port LCD.COM0
COM1: U11.15(COM1) ; port LCD.COM1
COM2: U11.14(COM2) ; port LCD.COM2
COM3: U11.13(COM3) ; port LCD.COM3
SEG0: U11.1(SEG0) ; port LCD.SEG0  [project net PC4]
SEG1: U11.2(SEG1) ; port LCD.SEG1  [project net PC5]
SEG2: U11.3(SEG2) ; port LCD.SEG2  [project net PB1]
SEG3: U11.4(SEG3) ; port LCD.SEG3  [project net PE7]
SEG4: U11.5(SEG4) ; port LCD.SEG4  [project net PE8]
SEG5: U11.6(SEG5) ; port LCD.SEG5  [project net PE9]
SEG6: U11.7(SEG6) ; port LCD.SEG6  [project net PB11]
SEG7: U11.8(SEG7) ; port LCD.SEG7  [project net PB14]
SEG8: U11.9(SEG8) ; port LCD.SEG8  [project net PB15]
SEG9: U11.10(SEG9) ; port LCD.SEG9  [project net PD8]
SEG10: U11.11(SEG10) ; port LCD.SEG10  [project net PD9]
SEG11: U11.12(SEG11) ; port LCD.SEG11  [project net PD12]
SEG12: U11.17(SEG12) ; port LCD.SEG12  [project net PD13]
SEG13: U11.18(SEG13) ; port LCD.SEG13  [project net PC6]
SEG14: U11.19(SEG14) ; port LCD.SEG14  [project net PC8]
SEG15: U11.20(SEG15) ; port LCD.SEG15  [project net PC9]
SEG16: U11.21(SEG16) ; port LCD.SEG16  [project net PC10]
SEG17: U11.22(SEG17) ; port LCD.SEG17  [project net PD0]
SEG18: U11.23(SEG18) ; port LCD.SEG18  [project net PD1]
SEG19: U11.24(SEG19) ; port LCD.SEG19  [project net PD3]
SEG20: U11.25(SEG20) ; port LCD.SEG20  [project net PD4]
SEG21: U11.26(SEG21) ; port LCD.SEG21  [project net PD5]
SEG22: U11.27(SEG22) ; port LCD.SEG22  [project net PD6]
SEG23: U11.28(SEG23) ; port LCD.SEG23  [project net PC11]

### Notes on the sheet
- Segment LCD

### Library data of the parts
HW9 = MCD-03173: Socket_IC, DIP28, DILB series, pitch 2.54mm, T=5.1mm; Part_Preference: Recommended; Manufacturer: AMPHENOL ICC; ShowFields: YES; ID: 5289
U11 = MCD-03134: Segment LCD, 4 COM, 24 data, DIP28 package; Part_Type: Display; Part_Preference: Recommended; Manufacturer: HZDSLCD; ShowFields: YES; ID: 5250

## Sheet STLINK_V2EC.SchDoc: STLINK-V2EC
size A3; Date: Not used; ApprovedBy: Not used; CheckedBy: Not used; Author: Not used; CompanyName: STMicroelectronics; DrawnBy: Not used; Engineer: Not used; Organization: Not used; Address1: Not used; Address2: Not used; Address3: Not used; Address4: Not used; DocumentNumber: Not used; Revision: V0.1; SheetNumber: 10; SheetTotal: 11
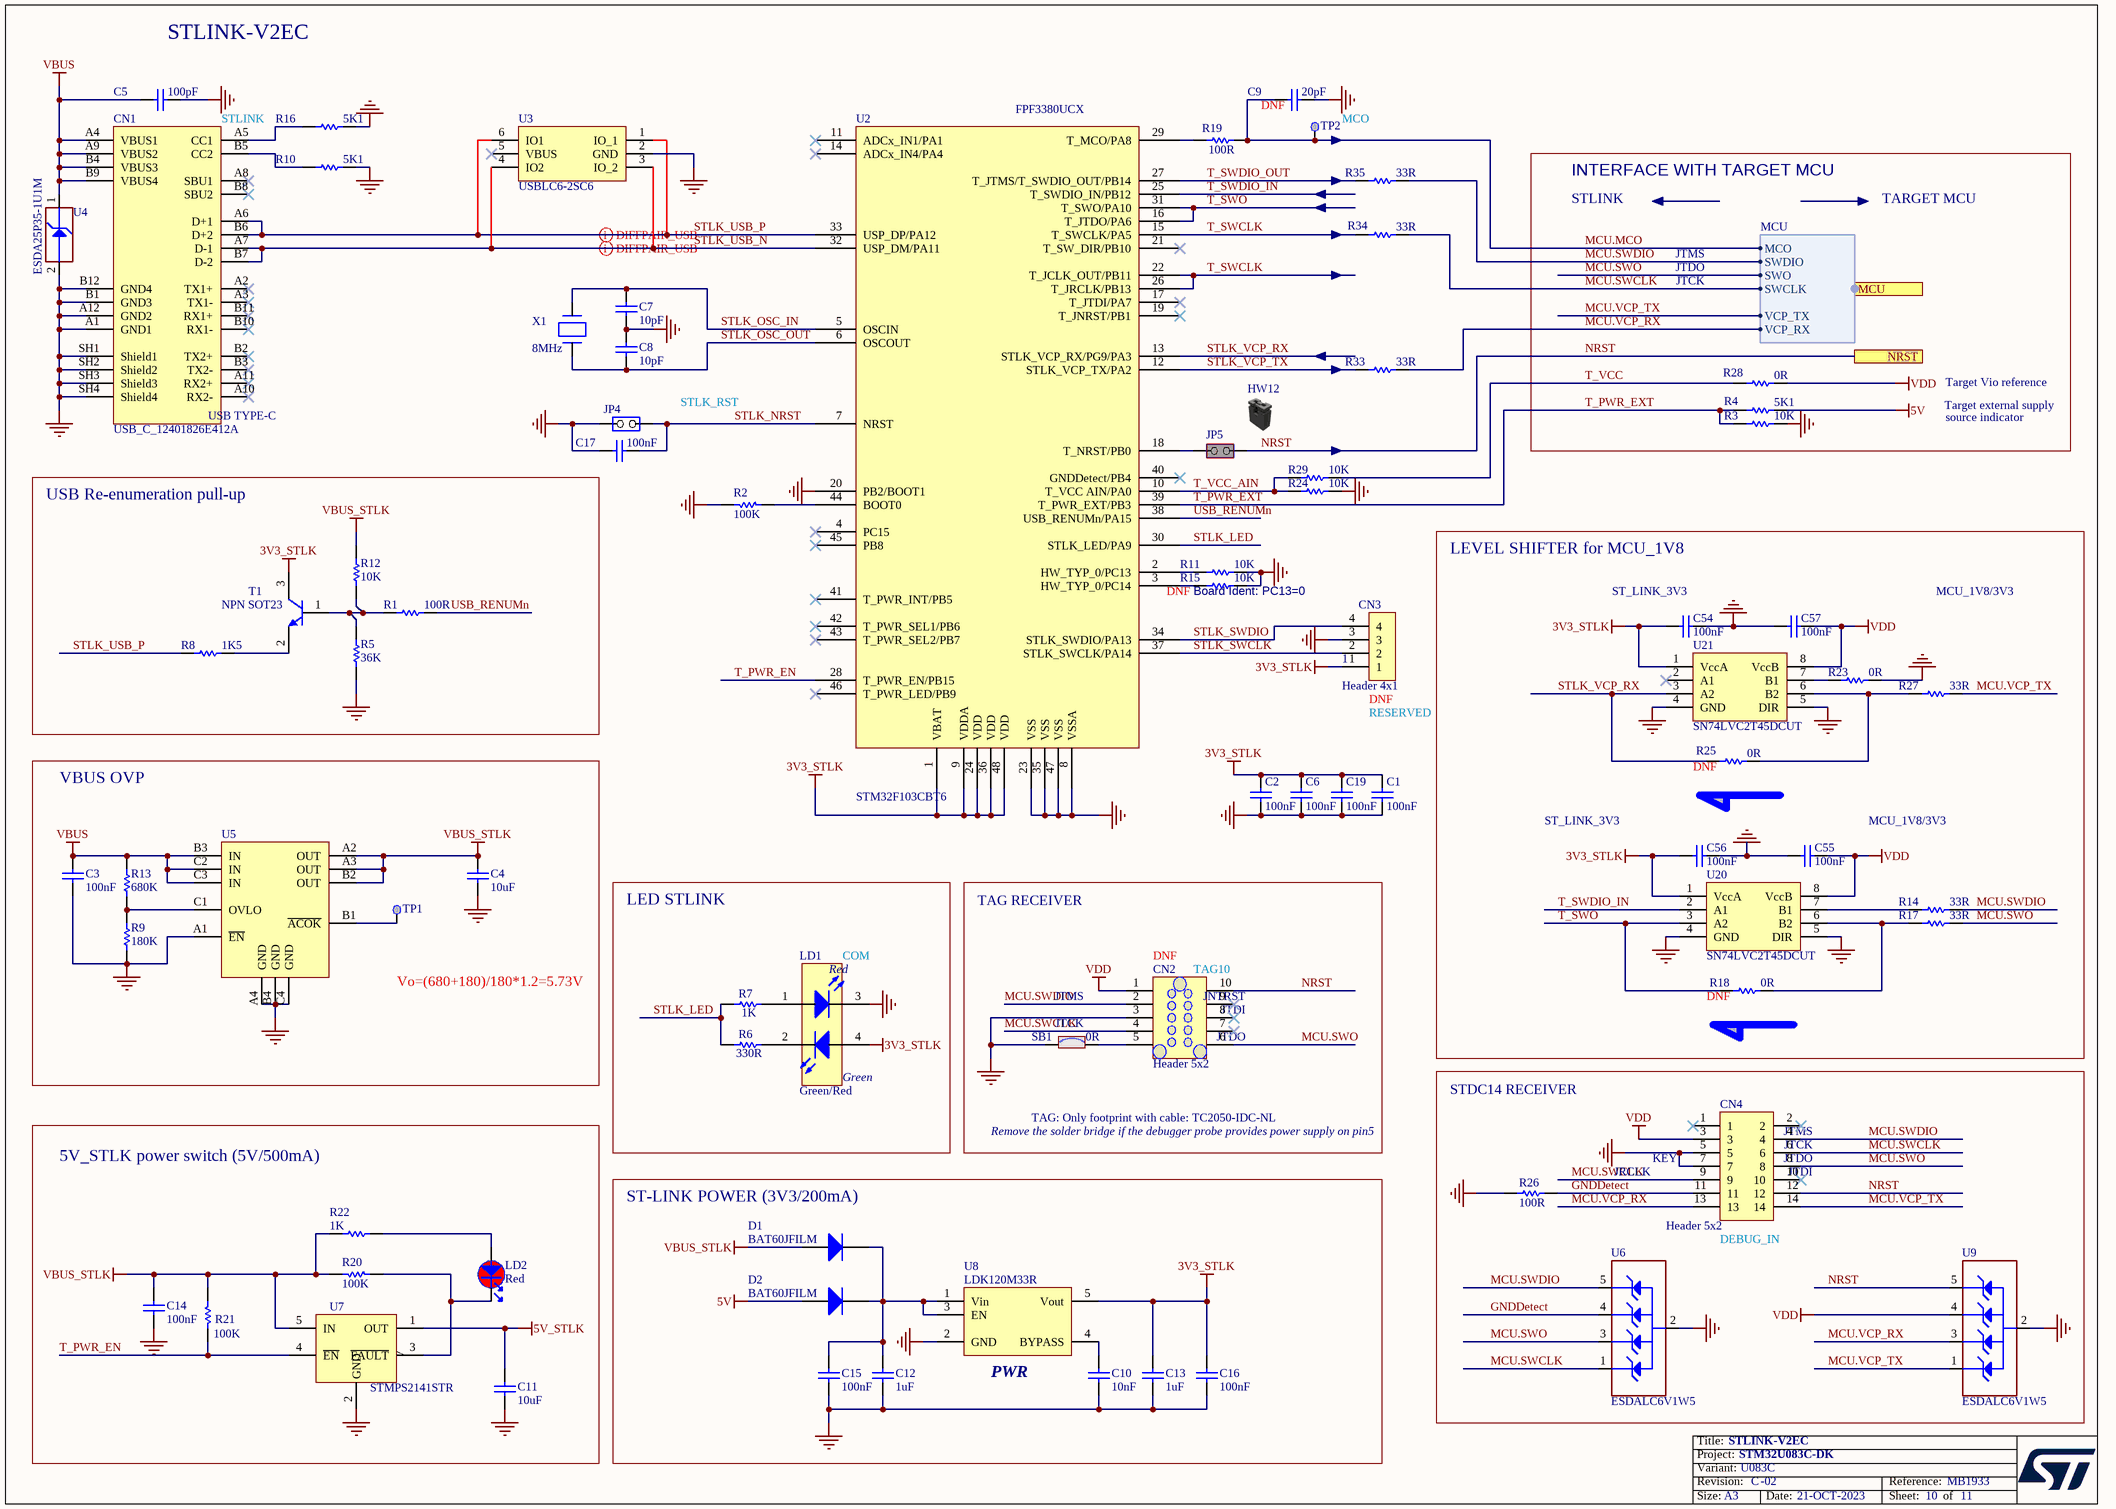
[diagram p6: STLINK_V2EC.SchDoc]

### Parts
C1  value 100nF  [C0402]  (hidden comment: Capacitor)
C2  value 100nF  [C0402]  (hidden comment: Capacitor)
C3  value 100nF  [C0603]  (hidden comment: Capacitor)
C4  value 10uF  [C0603]  (hidden comment: Capacitor)
C5  value 100pF  [C0402]  (hidden comment: Capacitor)
C6  value 100nF  [C0402]  (hidden comment: Capacitor)
C7  value 10pF  [C0402]  (hidden comment: Capacitor)
C8  value 10pF  [C0402]  (hidden comment: Capacitor)
C9  value 20pF  [C0402]  (hidden comment: Capacitor)
C10  value 10nF  [C0402]  (hidden comment: Capacitor)
C11  value 10uF  [C0603]  (hidden comment: Capacitor)
C12  value 1uF  [C0603]  (hidden comment: Capacitor)
C13  value 1uF  [C0603]  (hidden comment: Capacitor)
C14  value 100nF  [C0402]  (hidden comment: Capacitor)
C15  value 100nF  [C0402]  (hidden comment: Capacitor)
C16  value 100nF  [C0402]  (hidden comment: Capacitor)
C17  value 100nF  [C0402]  (hidden comment: Capacitor)
C19  value 100nF  [C0402]  (hidden comment: Capacitor)
C54  value 100nF  [C0402]  (hidden comment: Capacitor)
C55  value 100nF  [C0402]  (hidden comment: Capacitor)
C56  value 100nF  [C0402]  (hidden comment: Capacitor)
C57  value 100nF  [C0402]  (hidden comment: Capacitor)
CN1  value USB_C_12401826E412A  [CON_USB-TYPEC_AMPHENOL_12401826E412A]  (hidden comment: USB_TYPE_C_Receptacle)
CN2  value Header 5x2  [CON_TAG-C_TC2050-IDC-NL]  (hidden comment: Tag-10-C)  (no BOM)
CN3  Header 4x1  [CON_SAMTEC_TSW-104-07-G-S]
CN4  value Header 5x2  [CON_STDC14_Receiver_MEDIUM_WITH_MIPI10_3D]  (hidden comment: Header 7x2)
D1  BAT60JFILM  [DIO_SOD323]
D2  BAT60JFILM  [DIO_SOD323]
HW12  Shunt Black 2.54mm  (value not drawn)  (mechanical)
JP4  Jumper_Header 2x1  [CON_SAMTEC_TSW-102-07-G-S]  (value not drawn)
JP5  Jumper_Header 2x1 Fitted  [CON_SAMTEC_TSW-102-07-G-S]  (value not drawn)
LD1  value Green/Red  [LED_BI-GR_WE-150141SV73110]  (hidden comment: LED_BICOLOR)
LD2  value Red  [LED_0402_KINGBRIGHT_KPHHS-1005SURCK_HYPER-RED_1A2K_H0P5]  (hidden comment: LED_red)
R1  value 100R  [R0402]  (hidden comment: Resistor)
R2  value 100K  [R0402]  (hidden comment: Resistor)
R3  value 10K  [R0402]  (hidden comment: Resistor)
R4  value 5K1  [R0402]  (hidden comment: Resistor)
R5  value 36K  [R0402]  (hidden comment: Resistor)
R6  value 330R  [R0402]  (hidden comment: Resistor)
R7  value 1K  [R0402]  (hidden comment: Resistor)
R8  value 1K5  [R0402]  (hidden comment: Resistor)
R9  value 180K  [R0402]  (hidden comment: Resistor)
R10  value 5K1  [R0402]  (hidden comment: Resistor)
R11  value 10K  [R0402]  (hidden comment: Resistor)
R12  value 10K  [R0402]  (hidden comment: Resistor)
R13  value 680K  [R0402]  (hidden comment: Resistor)
R14  value 33R  [R0402]  (hidden comment: Resistor)
R15  value 10K  [R0402]  (hidden comment: Resistor)
R16  value 5K1  [R0402]  (hidden comment: Resistor)
R17  value 33R  [R0402]  (hidden comment: Resistor)
R18  value 0R  [R0402]  (hidden comment: Resistor)
R19  value 100R  [R0402]  (hidden comment: Resistor)
R20  value 100K  [R0402]  (hidden comment: Resistor)
R21  value 100K  [R0402]  (hidden comment: Resistor)
R22  value 1K  [R0402]  (hidden comment: Resistor)
R23  value 0R  [R0402]  (hidden comment: Resistor)
R24  value 10K  [R0402]  (hidden comment: Resistor)
R25  value 0R  [R0402]  (hidden comment: Resistor)
R26  value 100R  [R0402]  (hidden comment: Resistor)
R27  value 33R  [R0402]  (hidden comment: Resistor)
R28  value 0R  [R0402]  (hidden comment: Resistor)
R29  value 10K  [R0402]  (hidden comment: Resistor)
R33  value 33R  [R0402]  (hidden comment: Resistor)
R34  value 33R  [R0402]  (hidden comment: Resistor)
R35  value 33R  [R0402]  (hidden comment: Resistor)
SB1  value 0R  [SOLDER-BRIDGE_R0603-0R]  (hidden comment: SB_ON)
T1  value NPN SOT23  [NPN_SOT23]  (hidden comment: 9013-SOT23)
TP1  Test Point  [TP_SMD_1MM]  (value not drawn)  (no BOM)
TP2  Test Point  [TP_SMD_1MM]  (value not drawn)  (no BOM)
U2  value STM32F103CBT6  [ICC_LQFP48_7X7_P050]  (hidden comment: STLINK-V2EC_Old)
U3  USBLC6-2SC6  [ESD_SOT23-6L]
U4  value ESDA25P35-1U1M  [ESD_QFN1610_2N_1K_2A]  (hidden comment: ESD-TRANSIL)
U5  FPF3380UCX  [ICC_WLCSP12_1P858x1P318_P040]
U6  ESDALC6V1W5  [ESD_SOT323-5L]
U7  STMPS2141STR  [MOS_SOT23-5L]
U8  LDK120M33R  [REG_SOT23-5L]
U9  ESDALC6V1W5  [ESD_SOT323-5L]
U20  SN74LVC2T45DCUT  [ICC_VSSOP8_DCU_R-PDSO-G8_2X2P30_P050]
U21  SN74LVC2T45DCUT  [ICC_VSSOP8_DCU_R-PDSO-G8_2X2P30_P050]
X1  value 8MHz  [CRY_NX3225GD_2P]  (hidden comment: XTAL_2_PINS)

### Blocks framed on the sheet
INTERFACE WITH TARGET MCU: R3 R4 R28
USB Re-enumeration pull-up: R1 R5 R8 R12 T1
LEVEL SHIFTER for MCU_1V8: C54-C57 R14 R17 R18 R23 R25 R27 U20 U21
VBUS OVP: C3 C4 R9 R13 TP1 U5
LED STLINK: LD1 R6 R7
TAG RECEIVER: CN2 SB1
STDC14 RECEIVER: CN4 R26 U6 U9
5V_STLK power switch (5V/500mA): C11 C14 LD2 R20-R22 U7

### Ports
MCU (harness MCU), NRST

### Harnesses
MCU: MCO, SWDIO, SWO, VCP_TX, SWCLK, VCP_RX

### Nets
3V3_STLK: C1.1 C2.1 C6.1 C13.2 C16.2 C19.1 C54.2 C56.2 CN3.1 LD1.4(Green_anode) T1.3(C) U2.1(VBAT) U2.9(VDDA) U2.24(VDD) U2.36(VDD) U2.48(VDD) U8.5(Vout) U20.1(VccA) U21.1(VccA)
5V: D2.1(A) R4.2
5V_STLK: C11.2 U7.1(OUT)
GND: C1.2 C2.2 C3.2 C4.1 C5.2 C6.2 C7.1 C8.2 C9.1 C10.1 C11.1 C12.1 C13.1 C14.1 C15.1 C16.1 C17.1 C19.2 C54.1 C55.2 C56.1 C57.2 CN1.A1(GND1) CN1.A12(GND2) CN1.B1(GND3) CN1.B12(GND4) CN1.SH1(Shield1) CN1.SH2(Shield2) CN1.SH3(Shield3) CN1.SH4(Shield4) CN2.3 CN3.3 CN4.5 CN4.7 JP4.2(NO) LD1.3(RED_cathode) R2.1 R3.2 R5.1 R9.1 R10.2 R11.2 R15.2 R16.2 R23.2 R24.2 R26.1 SB1.1 U2.8(VSSA) U2.20(PB2/BOOT1) U2.23(VSS) U2.35(VSS) U2.47(VSS) U3.2(GND) U4.2(GND) U5.A1(~{EN}) U5.A4(GND) U5.B4(GND) U5.C4(GND) U6.2(GND) U7.2(GND) U8.2(GND) U9.2(GND) U20.4(GND) U20.5(DIR) U21.4(GND) U21.5(DIR)
VBUS: C3.1 C5.1 CN1.A4(VBUS1) CN1.A9(VBUS2) CN1.B4(VBUS3) CN1.B9(VBUS4) R13.2 U4.1(IO1) U5.B3(IN) U5.C2(IN) U5.C3(IN)
VBUS_STLK: C4.2 C14.2 D1.1(A) R12.2 R20.2 R21.2 R22.2 U5.A2(OUT) U5.A3(OUT) U5.B2(OUT) U7.5(IN)
VDD: C55.1 C57.1 CN2.1 CN4.3 R28.2 U9.4(IO3) U20.8(VccB) U21.8(VccB)
GNDDetect: CN4.11 R26.2 U6.4(IO3)
MCU.MCO: C9.2 R19.2 TP2.1 ; port MCU.MCO
MCU.SWCLK: CN2.4 CN4.6 CN4.9 R34.2 U6.1(IO1) ; port MCU.SWCLK
MCU.SWDIO: CN2.2 CN4.4 R14.2 R35.2 U6.5(IO4) ; port MCU.SWDIO
MCU.SWO: CN2.6 CN4.8 R17.2 U6.3(IO2) ; port MCU.SWO
MCU.VCP_RX: CN4.13 R33.2 U9.3(IO2) ; port MCU.VCP_RX  [project net ARD_D0]
MCU.VCP_TX: CN4.14 R27.2 U9.1(IO1) ; port MCU.VCP_TX  [project net ARD_D1]
NRST: CN2.10 CN4.12 JP5.1(COMMON) U9.5(IO4) ; port NRST
STLK_LED: R6.1 R7.2 U2.30(STLK_LED/PA9)
STLK_NRST: C17.2 JP4.1(COMMON) U2.7(NRST)
STLK_OSC_IN: C7.2 U2.5(OSCIN) X1.2(X2)
STLK_OSC_OUT: C8.1 U2.6(OSCOUT) X1.1(X1)
STLK_SWCLK: CN3.2 U2.37(STLK_SWCLK/PA14)
STLK_SWDIO: CN3.4 U2.34(STLK_SWDIO/PA13)
STLK_USB_N: CN1.A7(D-1) CN1.B7(D-2) U2.32(USP_DM/PA11) U3.3(IO_2) U3.4(IO2)
STLK_USB_P: CN1.A6(D+1) CN1.B6(D+2) R8.1 U2.33(USP_DP/PA12) U3.1(IO_1) U3.6(IO1)
STLK_VCP_RX: R25.1 U2.13(STLK_VCP_RX/PG9/PA3) U21.3(A2)
STLK_VCP_TX: R33.1 U2.12(STLK_VCP_TX/PA2)
T_PWR_EN: R21.1 U2.28(T_PWR_EN/PB15) U7.4(~{EN})
T_PWR_EXT: R3.1 R4.1 U2.39(T_PWR_EXT/PB3)
T_SWCLK: R34.1 U2.15(T_SWCLK/PA5) U2.22(T_JCLK_OUT/PB11) U2.26(T_JRCLK/PB13)
T_SWDIO_IN: U2.25(T_SWDIO_IN/PB12) U20.2(A1)
T_SWDIO_OUT: R35.1 U2.27(T_JTMS/T_SWDIO_OUT/PB14)
T_SWO: R18.1 U2.16(T_JTDO/PA6) U2.31(T_SWO/PA10) U20.3(A2)
T_VCC: R28.1 R29.2
T_VCC_AIN: R24.1 R29.1 U2.10(T_VCC_AIN/PA0)
USB_RENUMn: R1.2 U2.38(USB_RENUMn/PA15)
NetC10_2: C10.2 U8.4(BYPASS)
NetC12_2: C12.2 C15.2 D1.2(K) D2.2(K) U8.1(Vin) U8.3(EN)
NetCN1_A5: CN1.A5(CC1) R16.1
NetCN1_B5: CN1.B5(CC2) R10.1
NetCN2_5: CN2.5 SB1.2
NetJP5_2: JP5.2(NO) U2.18(T_NRST/PB0)
NetLD1_1: LD1.1(Red_anode) R7.1
NetLD1_2: LD1.2(Green_cathode) R6.2
NetLD2_1: LD2.1 R22.1
NetLD2_2: LD2.2 R20.1 U7.3(~{FAULT})
NetR1_1: R1.1 R5.2 R12.1 T1.1(B)
NetR2_2: R2.2 U2.44(BOOT0)
NetR8_2: R8.2 T1.2(E)
NetR9_2: R9.2 R13.1 U5.C1(OVLO)
NetR11_1: R11.1 U2.2(HW_TYP_0/PC13)
NetR14_1: R14.1 U20.7(B1)
NetR15_1: R15.1 U2.3(HW_TYP_0/PC14)
NetR17_1: R17.1 R18.2 U20.6(B2)
NetR19_1: R19.1 U2.29(T_MCO/PA8)
NetR23_1: R23.1 U21.7(B1)
NetR25_2: R25.2 R27.1 U21.6(B2)
NetTP1_1: TP1.1 U5.B1(~{ACOK})

Not connected (* = marked no-connect by the designer): CN1 A2(TX1+)* A3(TX1-)* A8(SBU1)* A10(RX2-)* A11(RX2+)* B2(TX2+)* B3(TX2-)* B8(SBU2)* B10(RX1-)* B11(RX1+)*; CN2 7* 8* 9*; CN4 1* 2* 10*; U2 4(PC15)* 11(ADCx_IN1/PA1)* 14(ADCx_IN4/PA4)* 17(T_JTDI/PA7)* 19(T_JNRST/PB1)* 21(T_SW_DIR/PB10)* 40(GNDDetect/PB4)* 41(T_PWR_INT/PB5)* 42(T_PWR_SEL1/PB6)* 43(T_PWR_SEL2/PB7)* 45(PB8)* 46(T_PWR_LED/PB9)*; U3 5(VBUS)*; U21 2(A1)*

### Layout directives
differential pair; rule Impedance Constraint [Min = 85.00    Max = 95.00    ]: STLK_USB_N, STLK_USB_P

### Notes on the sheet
- STLINK-V2EC
- (near C9) DNF
- STLINK
- MCO
- TARGET MCU
- JTMS
- JTDO
- JTCK
- (near JP4) STLK_RST
- Target external supply
- Target Vio reference
- source indicator
- DNF
- (near R15) Board Ident: PC13=0
- ST_LINK_3V3
- MCU_1V8/3V3
- (near CN3) 1
- (near CN3) DNF
- (near CN3) RESERVED
- (near R25) DNF
- Vo=(680+180)/180*1.2=5.73V
- (near LD1) COM
- (near CN2) DNF
- (near CN2) TAG10
- (near SB1) JTCK
- (near CN2) JTDO
- (near CN2) JTDI
- (near CN2) JNTRST
- (near R18) DNF
- TAG: Only footprint with cable: TC2050-IDC-NL
- Remove the solder bridge if the debugger probe provides power supply on pin5
- (near CN4) KEY
- (near CN4) JRCLK
- (near CN4) JTCK
- (near CN4) JTMS
- (near CN4) JTDI
- (near CN4) JTDO
- (near D1) ST-LINK POWER (3V3/200mA)
- (near CN4) DEBUG_IN
- (near U8) PWR

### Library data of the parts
C1 C2 C6 C15-C17 C19 C54-C57 = MCD-00006: as C22 on sheet Power
C3 = MCD-01099: Capacitor, MLCC, 100nF, 50V, X7R, +/-10%, 0603, T=0.8mm; Manufacturer_Part_Number: CC0603KRX7R9BB104; Manufacturer: YAGEO; BMS_Part_Number: 9142278; Part_Preference: Recommended; Order_Code_RS: 669-8767; Component_Country_Of_Origin: China; ShowFields: YES; ID: 3397
C4 C11 = MCD-00099: Capacitor, MLCC, 10uF, 10V, X5R, +/-10%, 0603, T=0.8mm; Part_Preference: Recommended; Manufacturer: MURATA; Manufacturer_Part_Number: GRM188R61A106KE69D; Partial_Alternate_Internal_Part_Number: MCD-03152; Order_Code_RS: 2494233; Component_Country_Of_Origin: Japan°°; ShowFields: YES; ID: 2770
C5 = MCD-00205: Capacitor, MLCC, 100pF, 50V, NPO, +/-5%, 0402, T=0.5mm; Part_Preference: Recommended; Manufacturer: YAGEO; Manufacturer_Part_Number: CC0402JRNPO9BN101; Component_Country_Of_Origin: China; ShowFields: YES; ID: 2658
C7 C8 = MCD-00015: Capacitor, MLCC, 10pF, 50V, NPO, +/-5%, 0402, T=0.5mm; Manufacturer_Part_Number: CC0402JRNPO9BN100; Manufacturer: YAGEO; Part_Preference: Recommended; Order_Code_RS: 3019160RL; Component_Country_Of_Origin: China; ShowFields: YES; ID: 2465
C9 = MCD-00016: Capacitor, MLCC, 20pF, 50V, NPO, +/- 5%, 0402, T=0.5mm; Manufacturer_Part_Number: CC0402JRNPO9BN200; Manufacturer: YAGEO; Part_Preference: Recommended; Component_Country_Of_Origin: China; ShowFields: YES; ID: 2479
C10 = MCD-02198: as C18 on sheet Power
C12 C13 = MCD-00010: as C43 on sheet STM32_microcontroller_IOs
C14 = MCD-00006: as C40 on sheet STM32_microcontroller_IOs
CN1 = MCD-03232: USB_TypeC, 24 pins, RA, SMD, T=2.96mm; Part_Type: Connector; Part_Preference: Recommended; Manufacturer: AMPHENOL ICC; Manufacturer_Part_Number: 12401826E412A; Component_Country_Of_Origin: China°; ShowFields: YES; ID: 5348
CN2 = MCD-00031: Header_Plug-of-nails, 5x2, 1.27mm, No legs; Part_Type: Connector; Part_Preference: Recommended; ShowFields: YES; ID: 2486
CN3 = MCD-00029: Header, 4x1, 2.54mm, VR, TH, T=5.84mm/2.54mm; Manufacturer_Part_Number: TSW-104-07-G-S; Manufacturer: SAMTEC; Part_Type: Connector; Part_Preference: Recommended; Order_Code_RS: 2667450; Component_Country_Of_Origin: China, Costa Rica, Malaysia, USA, Vietnam; ShowFields: YES; ID: 2487
CN4 = MCD-01226: Header, 5x2, 1.27mm, VR, SMD, T=5.97mm/3.05mm; Part_Type: Connector; Manufacturer_Part_Number: FTSH-105-01-L-DV-K; Manufacturer: SAMTEC; Part_Preference: Recommended; Partial_Alternate_Internal_Part_Number: MCD-02956; Order_Code_RS: 159-2332; Component_Country_Of_Origin: China, Costa Rica, Malaysia, United States, Vietnam; ShowFields: YES; ID: 3265
D1 D2 = MCD-00034: Diode, Schottky, 0V53, 1A, 10V, SOD-323; Manufacturer: STMICROELECTRONICS; BMS_Part_Number: 9151097; Part_Preference: Recommended; Manufacturer_HQ_COO: EU; Component_Country_Of_Origin: China; ShowFields: YES; ID: 2483; Order_Code_RS: 714-6879
HW12 = MCD-00043: as HW5 on sheet Power
JP4 = MCD-00045: Header, 2x1, 2.54mm, VR, TH, T=5.84mm/2.54mm; Part_Preference: Recommended; Part_Type: Connector; Manufacturer: SAMTEC; Manufacturer_Part_Number: TSW-102-07-G-S; Full_Alternate_Internal_Part_Number: MCD-02390; Partial_Alternate_Internal_Part_Number: MCD-02957, MCD-03720; Order_Code_RS: 2505044; Component_Country_Of_Origin: China, Costa Rica, Malaysia, USA, Vietnam; ShowFields: YES; ID: 2545
JP5 = MCD-00683: as JP7 on sheet Power
LD1 = MCD-02631: LED Bicolor, Green/Red, 2V, 20mA, 4-PLCC; Part_Type: Display; Part_Preference: Recommended; Manufacturer: WURTH ELEKTRONIK; Manufacturer_Part_Number: 150141SV73110; Order_Code_RS: 184-6963; Component_Country_Of_Origin: China; ShowFields: YES; ID: 4737
LD2 = MCD-00708: LED, Red, 1V95, 20mA, 0402; Part_Type: Display; Manufacturer_Part_Number: KPHHS-1005SURCK; Manufacturer: KINGBRIGHT; Part_Preference: Recommended; Component_Country_Of_Origin: Unknown; ShowFields: YES; ID: 3037; Order_Code_RS: 466-3633
R1 = MCD-00067: Resistor, 100R, 0402, +/- 1%, 1/16W; Manufacturer_Part_Number: RC0402FR-07100RL; Manufacturer: YAGEO; Part_Preference: Recommended; Order_Code_RS: 9239111; Component_Country_Of_Origin: China; ShowFields: YES; ID: 2527
R2 R20 R21 = MCD-00059: as R50 on sheet STM32_microcontroller_IOs
R3 R11 R15 R24 R29 = MCD-00053: Resistor, 10K, 0402, +/-1%, 1/16W; Manufacturer_Part_Number: RC0402FR-0710KL; Manufacturer: YAGEO; BMS_Part_Number: 9131590; Part_Preference: Recommended; Order_Code_RS: 9239359; Component_Country_Of_Origin: China; ShowFields: YES; ID: 2539
R4 R10 R16 = MCD-00333: Resistor, 5K1, 0402, +/-1%, 1/16W; Part_Preference: Recommended; Manufacturer: YAGEO; Manufacturer_Part_Number: RC0402FR-075K1L; Component_Country_Of_Origin: China; ShowFields: YES; ID: 2944
R5 = MCD-00069: Resistor, 36K, 0402, +/-1%, 1/16W; Manufacturer_Part_Number: RC0402FR-0736KL; Manufacturer: YAGEO; Part_Preference: Recommended; Order_Code_RS: 1458788; Component_Country_Of_Origin: China; ShowFields: YES; ID: 2523
R6 = MCD-00062: Resistor, 330R, 0402, +/-1%, 1/16W; Part_Preference: Recommended; Manufacturer: YAGEO; Manufacturer_Part_Number: RC0402FR-07330RL; Order_Code_RS: 9239170; Component_Country_Of_Origin: China; ShowFields: YES; ID: 2529
R7 = MCD-00061: Resistor, 1K, 0402, +/-1%,1/16W; Part_Preference: Recommended; Manufacturer: YAGEO; Manufacturer_Part_Number: RC0402FR-071KL; Order_Code_RS: 9239235; ShowFields: YES; ID: 2532; Component_Country_Of_Origin: China
R8 = MCD-00068: Resistor, 1K5, 0402, +/-1%, 1/16W; Manufacturer_Part_Number: RC0402FR-071K5L; Manufacturer: YAGEO; Part_Preference: Recommended; Order_Code_RS: 9239251; Component_Country_Of_Origin: China; ShowFields: YES; ID: 2524
R9 = MCD-00413: Resistor, 180K, 0402, +/-1%, 1/16W; Manufacturer_Part_Number: RC0402FR-07180KL; Manufacturer: YAGEO; Part_Preference: Recommended; Component_Country_Of_Origin: China; ShowFields: YES; ID: 2864
R12 = MCD-00053: Resistor, 10K, 0402, +/-1%, 1/16W; Manufacturer_Part_Number: RC0402FR-0710KL; Manufacturer: YAGEO; Part_Preference: Recommended; BMS_Part_Number: 9131590; Order_Code_RS: 9239359; Component_Country_Of_Origin: China; ShowFields: YES; ID: 2539
R13 = MCD-00513: Resistor, 680K, 0402, +/-1%, 1/16W; Manufacturer_Part_Number: RC0402FR-07680KL; Manufacturer: YAGEO; Part_Preference: Recommended; Component_Country_Of_Origin: China; ShowFields: YES; ID: 3227
R14 R17 R27 R33-R35 = MCD-00455: Resistor, 33R, 0402, +/-1%, 1/16W; Part_Preference: Recommended; Manufacturer: YAGEO; Manufacturer_Part_Number: RC0402FR-0733RL; Component_Country_Of_Origin: China; ShowFields: YES; ID: 2821
R18 R25 R28 = MCD-00052: as R44 on sheet Power
R19 R26 = MCD-00067: Resistor, 100R, 0402, +/- 1%, 1/16W; Part_Preference: Recommended; Manufacturer: YAGEO; Manufacturer_Part_Number: RC0402FR-07100RL; Order_Code_RS: 9239111; Component_Country_Of_Origin: China; ShowFields: YES; ID: 2527
R22 = MCD-00061: Resistor, 1K, 0402, +/-1%,1/16W; Manufacturer_Part_Number: RC0402FR-071KL; Manufacturer: YAGEO; Part_Preference: Recommended; Order_Code_RS: 9239235; Component_Country_Of_Origin: China; ShowFields: YES; ID: 2532
R23 = MCD-00052: as R52 on sheet STM32_microcontroller_IOs
SB1 = MCD-00071: Resistor, 0R, SB0603, 5%, 0.1W; Part_Preference: Recommended; Manufacturer: YAGEO; Manufacturer_Part_Number: RC0603JR-070RL; Manufacturer_HQ_COO: Unknown; ShowFields: YES; ID: 2521; Order_Code_RS: 199-5647; Component_Country_Of_Origin: China
T1 = MCD-00073: NPN Bipolar Transistor; Part_Type: IC; Manufacturer_Part_Number: BSR14; Manufacturer: ON SEMICONDUCTOR; Part_Preference: Recommended; Partial_Alternate_Internal_Part_Number: MCD-01737, MCD-03305, , MCD-02988; Component_Country_Of_Origin: Unknown; ShowFields: YES; ID: 2519
TP1 TP2 = MCD-00074: as TP3 on sheet Power
U2 = MCD-03056: MCU, ARM Cortex-M3 32-bit, 128KB Flash, 20KB RAM, No Crypto; Part_Type: IC; Part_Preference: Not recommended; Manufacturer: STMICROELECTRONICS; ShowFields: YES; ID: 5172; Component_Country_Of_Origin: Malaysia
U3 = MCD-00163: Very low capacitance ESD protection; Part_Type: IC; Manufacturer: STMICROELECTRONICS; BMS_Part_Number: 9151075; Part_Preference: Recommended; Manufacturer_HQ_COO: EU; Component_Country_Of_Origin: China; ShowFields: YES; ID: 2707
U4 = MCD-01207: Diode, ESD TVS, 22V, 200nA, 25V8, QFN1610; Manufacturer: STMICROELECTRONICS; BMS_Part_Number: 9179045; Part_Preference: Recommended; Manufacturer_HQ_COO: EU; Component_Country_Of_Origin: China; ShowFields: YES; ID: 3289; Order_Code_RS: 163-9774
U5 = MCD-03166: Power switch, 28 V / 5 A  OVP with Low On-resistance, Integrated TVS; Part_Type: IC; Part_Preference: Recommended; Manufacturer: ON SEMICONDUCTOR; Partial_Alternate_Internal_Part_Number: MCD-03058; ShowFields: YES; ID: 5282; Component_Country_Of_Origin: Philippines
U6 U9 = MCD-00136: Diode, ESD Transil, 3V, 1uA, 7V2, SOT323-5L; BMS_Part_Number: 9151112; Part_Preference: Recommended; Manufacturer: STMICROELECTRONICS; Manufacturer_HQ_COO: EU; Component_Country_Of_Origin: China; Order_Code_RS: 178-7373; ShowFields: YES; ID: 2731
U7 = MCD-00083: Enhanced single channel power switches with active low enable pin; Part_Type: IC; Manufacturer: STMICROELECTRONICS; BMS_Part_Number: 9159003; Part_Preference: Recommended; Manufacturer_HQ_COO: EU; Component_Country_Of_Origin: Malaysia; ShowFields: YES; ID: 2509
U8 = MCD-00663: LDO, 200mA, Low quiescent current very low noise LDO; Part_Type: IC; Manufacturer: STMICROELECTRONICS; BMS_Part_Number: 9176330; Part_Preference: Recommended; Manufacturer_HQ_COO: EU; Partial_Alternate_Internal_Part_Number: MCD-03279; Component_Country_Of_Origin: China; ShowFields: YES; ID: 3082; Order_Code_RS: 188-9202
U20 U21 = MCD-00264: IC, 5 Dual-Bit Dual-Supply bus transceiver with configurable voltage translation and 3-State outputs; Manufacturer: TEXAS INSTRUMENTS; BMS_Part_Number: 9169311; Part_Preference: Recommended; Component_Country_Of_Origin: Thailand; ShowFields: YES; ID: 2605; Order_Code_RS: 922-2870
X1 = MCD-00092: Crystal, 8MHz, 8pF, +/-20ppm, 500R, 3.2x2.5mm; Part_Type: Crystal_Osc; Manufacturer_Part_Number: NX3225GD-8MHZ-EXS00A-CG04874; Manufacturer: NDK; BMS_Part_Number: 9157029; Part_Preference: Recommended; Component_Country_Of_Origin: Unknown; ShowFields: YES; ID: 2776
